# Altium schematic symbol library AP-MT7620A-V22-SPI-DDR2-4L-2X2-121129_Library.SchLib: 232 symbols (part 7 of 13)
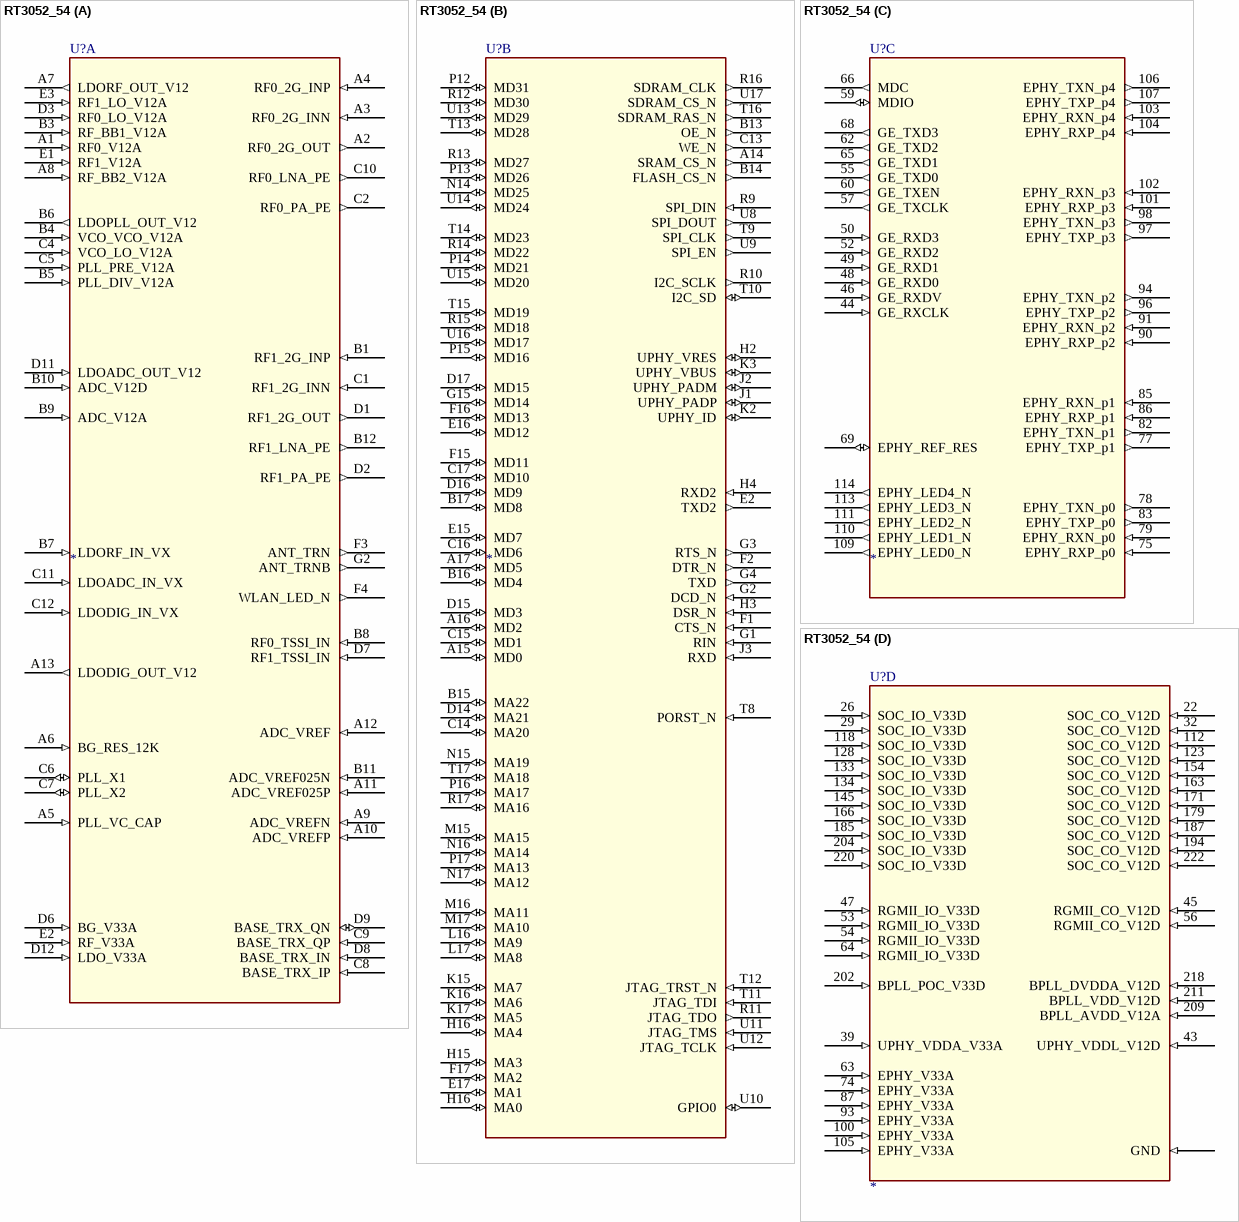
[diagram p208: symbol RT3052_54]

## RT3052_54
designator U?
footprint QFN285
part A pins: A1 RF0_V12A (in), A2 RF0_2G_OUT (out), A3 RF0_2G_INN (in), A4 RF0_2G_INP (in), A5 PLL_VC_CAP (in), A6 BG_RES_12K (in), A7 LDORF_OUT_V12 (out), A8 RF_BB2_V12A (in), A9 ADC_VREFN (in), A10 ADC_VREFP (in), A11 ADC_VREF025P (in), A12 ADC_VREF (in), A13 LDODIG_OUT_V12 (out), B1 RF1_2G_INP (in), B3 RF_BB1_V12A (in), B4 VCO_VCO_V12A (in), B5 PLL_DIV_V12A (in), B6 LDOPLL_OUT_V12 (out), B7 LDORF_IN_VX (in), B8 RF0_TSSI_IN (in), B9 ADC_V12A (in), B10 ADC_V12D (in), B11 ADC_VREF025N (in), B12 RF1_LNA_PE (out), C1 RF1_2G_INN (in), C2 RF0_PA_PE (out), C4 VCO_LO_V12A (in), C5 PLL_PRE_V12A (in), C6 PLL_X1 (io), C7 PLL_X2 (io), C8 BASE_TRX_IP (in), C9 BASE_TRX_QP (in), C10 RF0_LNA_PE (out), C11 LDOADC_IN_VX (in), C12 LDODIG_IN_VX (in), D1 RF1_2G_OUT (out), D2 RF1_PA_PE (out), D3 RF0_LO_V12A (in), D6 BG_V33A (in), D7 RF1_TSSI_IN (in), D8 BASE_TRX_IN (in), D9 BASE_TRX_QN (io), D11 LDOADC_OUT_V12 (in), D12 LDO_V33A (in), E1 RF1_V12A (in), E2 RF_V33A (in), E3 RF1_LO_V12A (in), F3 ANT_TRN (out), F4 WLAN_LED_N (out), G2 ANT_TRNB (out)
part B pins: A14 SRAM_CS_N (out), A15 MD0 (io), A16 MD2 (io), A17 MD5 (io), B13 OE_N (out), B14 FLASH_CS_N (out), B15 MA22 (io), B16 MD4 (io), B17 MD8 (io), C13 WE_N (out), C14 MA20 (io), C15 MD1 (io), C16 MD6 (io), C17 MD10 (io), D14 MA21 (io), D15 MD3 (io), D16 MD9 (io), D17 MD15 (io), E2 TXD2 (out), E15 MD7 (io), E16 MD12 (io), E17 MA1 (io), F1 CTS_N (in), F2 DTR_N (out), F15 MD11 (io), F16 MD13 (io), F17 MA2 (io), G1 RIN (in), G2 DCD_N (in), G3 RTS_N (out), G4 TXD (out), G15 MD14 (io), H2 UPHY_VRES (io), H3 DSR_N (in), H4 RXD2 (in), H15 MA3 (io), H16 MA4 (io), H16 MA0 (io), J1 UPHY_PADP (io), J2 UPHY_PADM (io), J3 RXD (in), K2 UPHY_ID (io), K3 UPHY_VBUS (io), K15 MA7 (io), K16 MA6 (io), K17 MA5 (io), L16 MA9 (io), L17 MA8 (io), M15 MA15 (io), M16 MA11 (io), M17 MA10 (io), N14 MD25 (io), N15 MA19 (io), N16 MA14 (io), N17 MA12 (io), P12 MD31 (io), P13 MD26 (io), P14 MD21 (io), P15 MD16 (io), P16 MA17 (io), P17 MA13 (io), R9 SPI_DIN (in), R10 I2C_SCLK (out), R11 JTAG_TDO (out), R12 MD30 (io), R13 MD27 (io), R14 MD22 (io), R15 MD18 (io), R16 SDRAM_CLK (out), R17 MA16 (io), T8 PORST_N (in), T9 SPI_CLK (out), T10 I2C_SD (io), T11 JTAG_TDI (in), T12 JTAG_TRST_N (in), T13 MD28 (io), T14 MD23 (io), T15 MD19 (io), T16 SDRAM_RAS_N (out), T17 MA18 (io), U8 SPI_DOUT (out), U9 SPI_EN (out), U10 GPIO0 (io), U11 JTAG_TMS (in), U12 JTAG_TCLK (in), U13 MD29 (io), U14 MD24 (io), U15 MD20 (io), U16 MD17 (io), U17 SDRAM_CS_N (out)
part C pins: 44 GE_RXCLK (in), 46 GE_RXDV (in), 48 GE_RXD0 (in), 49 GE_RXD1 (in), 50 GE_RXD3 (in), 52 GE_RXD2 (in), 55 GE_TXD0 (out), 57 GE_TXCLK (out), 59 MDIO (io), 60 GE_TXEN (out), 62 GE_TXD2 (out), 65 GE_TXD1 (out), 66 MDC (out), 68 GE_TXD3 (out), 69 EPHY_REF_RES (io), 75 EPHY_RXP_p0 (in), 77 EPHY_TXP_p1 (out), 78 EPHY_TXN_p0 (out), 79 EPHY_RXN_p0 (in), 82 EPHY_TXN_p1 (out), 83 EPHY_TXP_p0 (out), 85 EPHY_RXN_p1 (in), 86 EPHY_RXP_p1 (in), 90 EPHY_RXP_p2 (in), 91 EPHY_RXN_p2 (in), 94 EPHY_TXN_p2 (out), 96 EPHY_TXP_p2 (out), 97 EPHY_TXP_p3 (out), 98 EPHY_TXN_p3 (out), 101 EPHY_RXP_p3 (in), 102 EPHY_RXN_p3 (in), 103 EPHY_RXN_p4 (in), 104 EPHY_RXP_p4 (in), 106 EPHY_TXN_p4 (out), 107 EPHY_TXP_p4 (out), 109 EPHY_LED0_N (out), 110 EPHY_LED1_N (out), 111 EPHY_LED2_N (out), 113 EPHY_LED3_N (out), 114 EPHY_LED4_N (out)
part D pins: 22 SOC_CO_V12D (in), 26 SOC_IO_V33D (in), 29 SOC_IO_V33D (in), 32 SOC_CO_V12D (in), 39 UPHY_VDDA_V33A (in), 43 UPHY_VDDL_V12D (in), 45 RGMII_CO_V12D (in), 47 RGMII_IO_V33D (in), 53 RGMII_IO_V33D (in), 54 RGMII_IO_V33D (in), 56 RGMII_CO_V12D (in), 63 EPHY_V33A (in), 64 RGMII_IO_V33D (in), 74 EPHY_V33A (in), 87 EPHY_V33A (in), 93 EPHY_V33A (in), 100 EPHY_V33A (in), 105 EPHY_V33A (in), 112 SOC_CO_V12D (in), 118 SOC_IO_V33D (in), 123 SOC_CO_V12D (in), 128 SOC_IO_V33D (in), 133 SOC_IO_V33D (in), 134 SOC_IO_V33D (in), 145 SOC_IO_V33D (in), 154 SOC_CO_V12D (in), 163 SOC_CO_V12D (in), 166 SOC_IO_V33D (in), 171 SOC_CO_V12D (in), 179 SOC_CO_V12D (in), 185 SOC_IO_V33D (in), 187 SOC_CO_V12D (in), 194 SOC_CO_V12D (in), 202 BPLL_POC_V33D (in), 204 SOC_IO_V33D (in), 209 BPLL_AVDD_V12A (in), 211 BPLL_VDD_V12D (in), 218 BPLL_DVDDA_V12D (in), 220 SOC_IO_V33D (in), 222 SOC_CO_V12D (in), GND (in)

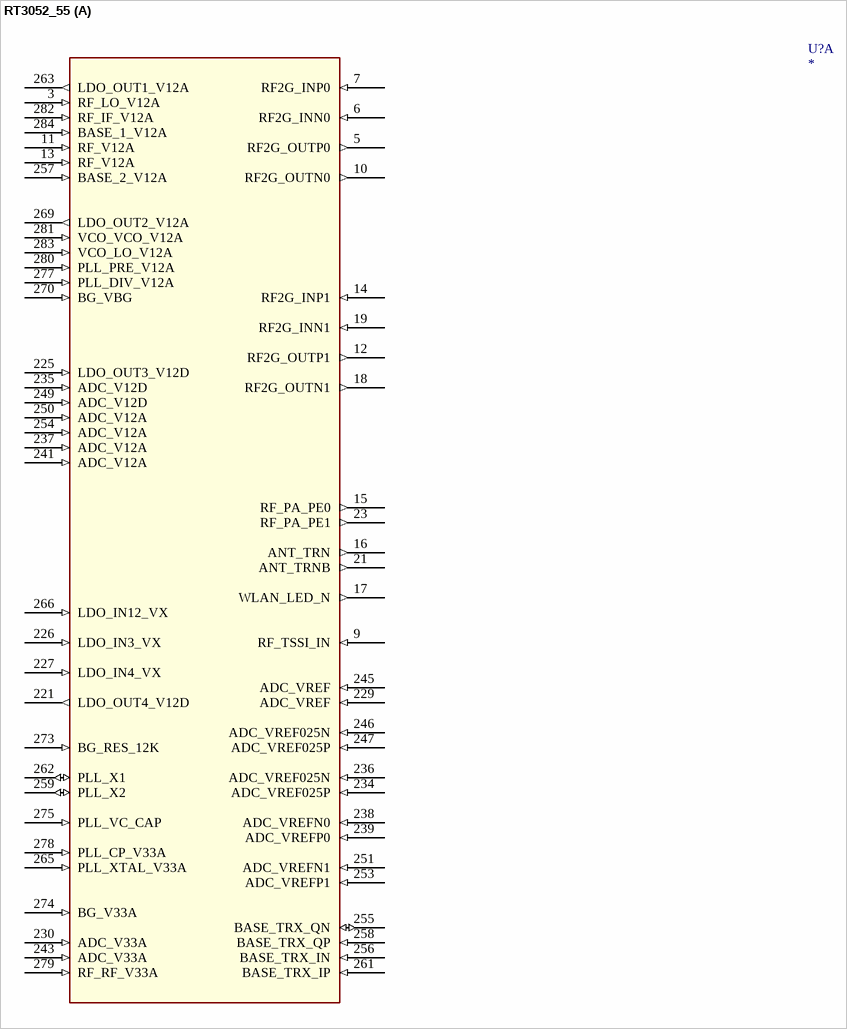
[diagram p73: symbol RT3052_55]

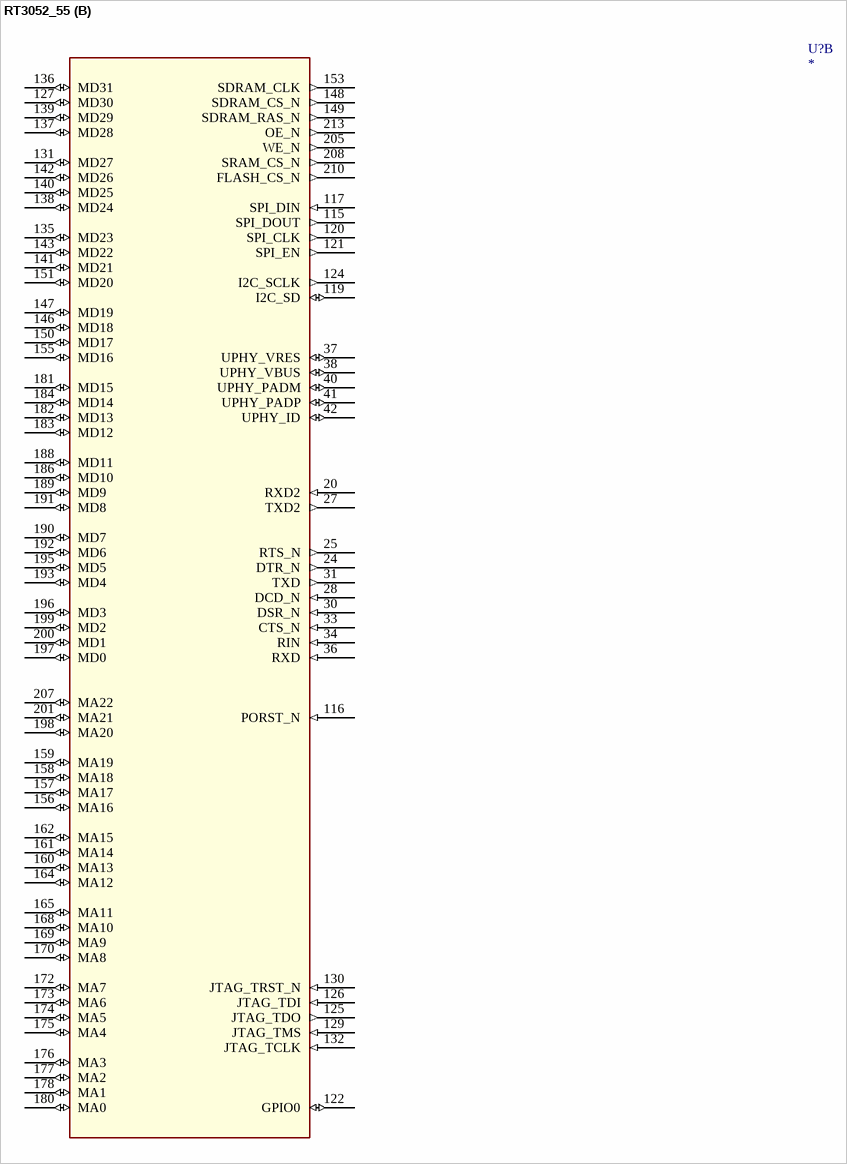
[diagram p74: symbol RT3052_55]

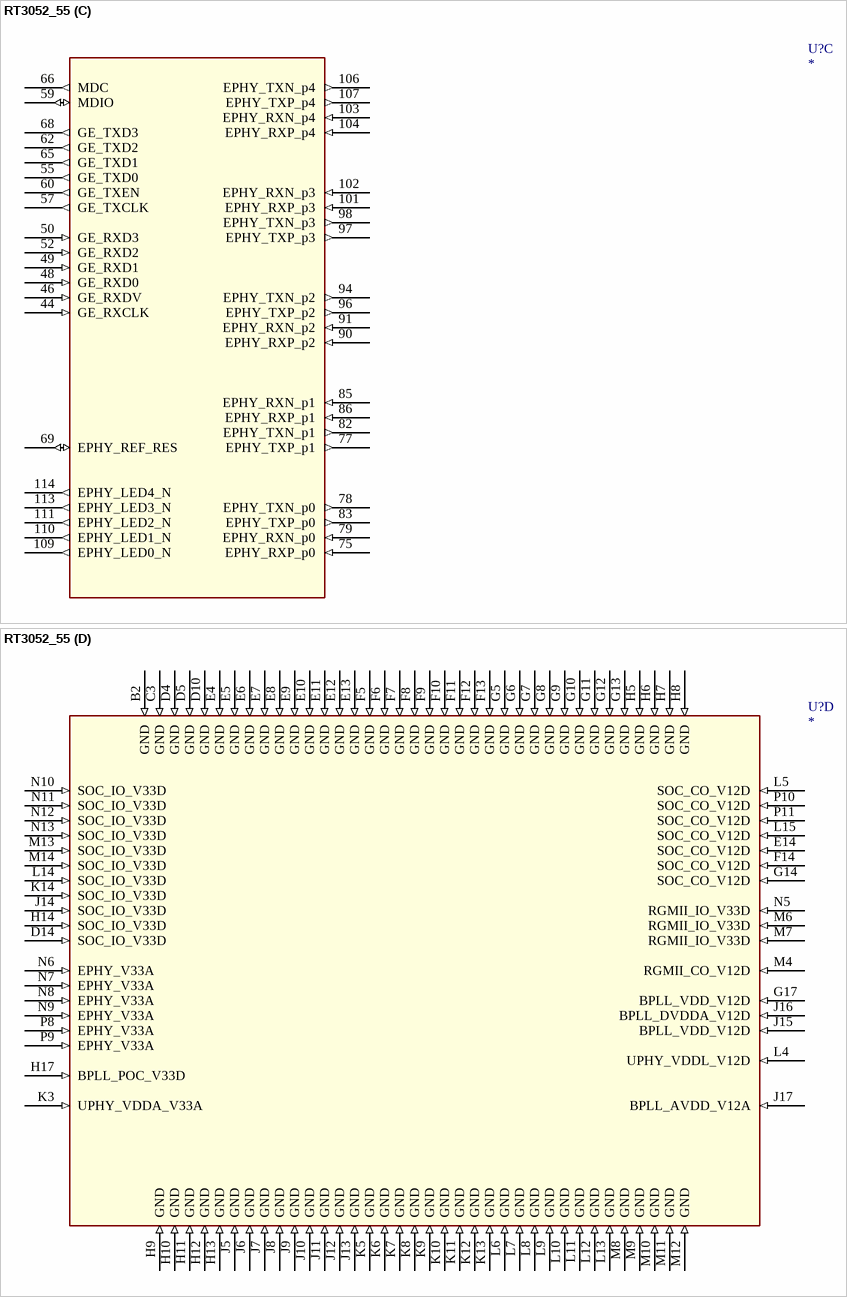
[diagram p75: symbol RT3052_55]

## RT3052_55
designator U?
footprint QFN285
part A pins: 3 RF_LO_V12A (in), 5 RF2G_OUTP0 (out), 6 RF2G_INN0 (in), 7 RF2G_INP0 (in), 9 RF_TSSI_IN (in), 10 RF2G_OUTN0 (out), 11 RF_V12A (in), 12 RF2G_OUTP1 (out), 13 RF_V12A (in), 14 RF2G_INP1 (in), 15 RF_PA_PE0 (out), 16 ANT_TRN (out), 17 WLAN_LED_N (out), 18 RF2G_OUTN1 (out), 19 RF2G_INN1 (in), 21 ANT_TRNB (out), 23 RF_PA_PE1 (out), 221 LDO_OUT4_V12D (out), 225 LDO_OUT3_V12D (in), 226 LDO_IN3_VX (in), 227 LDO_IN4_VX (in), 229 ADC_VREF (in), 230 ADC_V33A (in), 234 ADC_VREF025P (in), 235 ADC_V12D (in), 236 ADC_VREF025N (in), 237 ADC_V12A (in), 238 ADC_VREFN0 (in), 239 ADC_VREFP0 (in), 241 ADC_V12A (in), 243 ADC_V33A (in), 245 ADC_VREF (in), 246 ADC_VREF025N (in), 247 ADC_VREF025P (in), 249 ADC_V12D (in), 250 ADC_V12A (in), 251 ADC_VREFN1 (in), 253 ADC_VREFP1 (in), 254 ADC_V12A (in), 255 BASE_TRX_QN (io), 256 BASE_TRX_IN (in), 257 BASE_2_V12A (in), 258 BASE_TRX_QP (in), 259 PLL_X2 (io), 261 BASE_TRX_IP (in), 262 PLL_X1 (io), 263 LDO_OUT1_V12A (out), 265 PLL_XTAL_V33A (in), 266 LDO_IN12_VX (in), 269 LDO_OUT2_V12A (out), 270 BG_VBG (in), 273 BG_RES_12K (in), 274 BG_V33A (in), 275 PLL_VC_CAP (in), 277 PLL_DIV_V12A (in), 278 PLL_CP_V33A (in), 279 RF_RF_V33A (in), 280 PLL_PRE_V12A (in), 281 VCO_VCO_V12A (in), 282 RF_IF_V12A (in), 283 VCO_LO_V12A (in), 284 BASE_1_V12A (in)
part B pins: 20 RXD2 (in), 24 DTR_N (out), 25 RTS_N (out), 27 TXD2 (out), 28 DCD_N (in), 30 DSR_N (in), 31 TXD (out), 33 CTS_N (in), 34 RIN (in), 36 RXD (in), 37 UPHY_VRES (io), 38 UPHY_VBUS (io), 40 UPHY_PADM (io), 41 UPHY_PADP (io), 42 UPHY_ID (io), 115 SPI_DOUT (out), 116 PORST_N (in), 117 SPI_DIN (in), 119 I2C_SD (io), 120 SPI_CLK (out), 121 SPI_EN (out), 122 GPIO0 (io), 124 I2C_SCLK (out), 125 JTAG_TDO (out), 126 JTAG_TDI (in), 127 MD30 (io), 129 JTAG_TMS (in), 130 JTAG_TRST_N (in), 131 MD27 (io), 132 JTAG_TCLK (in), 135 MD23 (io), 136 MD31 (io), 137 MD28 (io), 138 MD24 (io), 139 MD29 (io), 140 MD25 (io), 141 MD21 (io), 142 MD26 (io), 143 MD22 (io), 146 MD18 (io), 147 MD19 (io), 148 SDRAM_CS_N (out), 149 SDRAM_RAS_N (out), 150 MD17 (io), 151 MD20 (io), 153 SDRAM_CLK (out), 155 MD16 (io), 156 MA16 (io), 157 MA17 (io), 158 MA18 (io), 159 MA19 (io), 160 MA13 (io), 161 MA14 (io), 162 MA15 (io), 164 MA12 (io), 165 MA11 (io), 168 MA10 (io), 169 MA9 (io), 170 MA8 (io), 172 MA7 (io), 173 MA6 (io), 174 MA5 (io), 175 MA4 (io), 176 MA3 (io), 177 MA2 (io), 178 MA1 (io), 180 MA0 (io), 181 MD15 (io), 182 MD13 (io), 183 MD12 (io), 184 MD14 (io), 186 MD10 (io), 188 MD11 (io), 189 MD9 (io), 190 MD7 (io), 191 MD8 (io), 192 MD6 (io), 193 MD4 (io), 195 MD5 (io), 196 MD3 (io), 197 MD0 (io), 198 MA20 (io), 199 MD2 (io), 200 MD1 (io), 201 MA21 (io), 205 WE_N (out), 207 MA22 (io), 208 SRAM_CS_N (out), 210 FLASH_CS_N (out), 213 OE_N (out)
part C pins: 44 GE_RXCLK (in), 46 GE_RXDV (in), 48 GE_RXD0 (in), 49 GE_RXD1 (in), 50 GE_RXD3 (in), 52 GE_RXD2 (in), 55 GE_TXD0 (out), 57 GE_TXCLK (out), 59 MDIO (io), 60 GE_TXEN (out), 62 GE_TXD2 (out), 65 GE_TXD1 (out), 66 MDC (out), 68 GE_TXD3 (out), 69 EPHY_REF_RES (io), 75 EPHY_RXP_p0 (in), 77 EPHY_TXP_p1 (out), 78 EPHY_TXN_p0 (out), 79 EPHY_RXN_p0 (in), 82 EPHY_TXN_p1 (out), 83 EPHY_TXP_p0 (out), 85 EPHY_RXN_p1 (in), 86 EPHY_RXP_p1 (in), 90 EPHY_RXP_p2 (in), 91 EPHY_RXN_p2 (in), 94 EPHY_TXN_p2 (out), 96 EPHY_TXP_p2 (out), 97 EPHY_TXP_p3 (out), 98 EPHY_TXN_p3 (out), 101 EPHY_RXP_p3 (in), 102 EPHY_RXN_p3 (in), 103 EPHY_RXN_p4 (in), 104 EPHY_RXP_p4 (in), 106 EPHY_TXN_p4 (out), 107 EPHY_TXP_p4 (out), 109 EPHY_LED0_N (out), 110 EPHY_LED1_N (out), 111 EPHY_LED2_N (out), 113 EPHY_LED3_N (out), 114 EPHY_LED4_N (out)
part D pins: B2 GND (in), C3 GND (in), D4 GND (in), D5 GND (in), D10 GND (in), D14 SOC_IO_V33D (in), E4 GND (in), E5 GND (in), E6 GND (in), E7 GND (in), E8 GND (in), E9 GND (in), E10 GND (in), E11 GND (in), E12 GND (in), E13 GND (in), E14 SOC_CO_V12D (in), F5 GND (in), F6 GND (in), F7 GND (in), F8 GND (in), F9 GND (in), F10 GND (in), F11 GND (in), F12 GND (in), F13 GND (in), F14 SOC_CO_V12D (in), G5 GND (in), G6 GND (in), G7 GND (in), G8 GND (in), G9 GND (in), G10 GND (in), G11 GND (in), G12 GND (in), G13 GND (in), G14 SOC_CO_V12D (in), G17 BPLL_VDD_V12D (in), H5 GND (in), H6 GND (in), H7 GND (in), H8 GND (in), H9 GND (in), H10 GND (in), H11 GND (in), H12 GND (in), H13 GND (in), H14 SOC_IO_V33D (in), H17 BPLL_POC_V33D (in), J5 GND (in), J6 GND (in), J7 GND (in), J8 GND (in), J9 GND (in), J10 GND (in), J11 GND (in), J12 GND (in), J13 GND (in), J14 SOC_IO_V33D (in), J15 BPLL_VDD_V12D (in), J16 BPLL_DVDDA_V12D (in), J17 BPLL_AVDD_V12A (in), K3 UPHY_VDDA_V33A (in), K5 GND (in), K6 GND (in), K7 GND (in), K8 GND (in), K9 GND (in), K10 GND (in), K11 GND (in), K12 GND (in), K13 GND (in), K14 SOC_IO_V33D (in), L4 UPHY_VDDL_V12D (in), L5 SOC_CO_V12D (in), L6 GND (in), L7 GND (in), L8 GND (in), L9 GND (in), L10 GND (in), L11 GND (in), L12 GND (in), L13 GND (in), L14 SOC_IO_V33D (in), L15 SOC_CO_V12D (in), M4 RGMII_CO_V12D (in), M6 RGMII_IO_V33D (in), M7 RGMII_IO_V33D (in), M8 GND (in), M9 GND (in), M10 GND (in), M11 GND (in), M12 GND (in), M13 SOC_IO_V33D (in), M14 SOC_IO_V33D (in), N5 RGMII_IO_V33D (in), N6 EPHY_V33A (in), N7 EPHY_V33A (in), N8 EPHY_V33A (in), N9 EPHY_V33A (in), N10 SOC_IO_V33D (in), N11 SOC_IO_V33D (in), N12 SOC_IO_V33D (in), N13 SOC_IO_V33D (in), P8 EPHY_V33A (in), P9 EPHY_V33A (in), P10 SOC_CO_V12D (in), P11 SOC_CO_V12D (in)

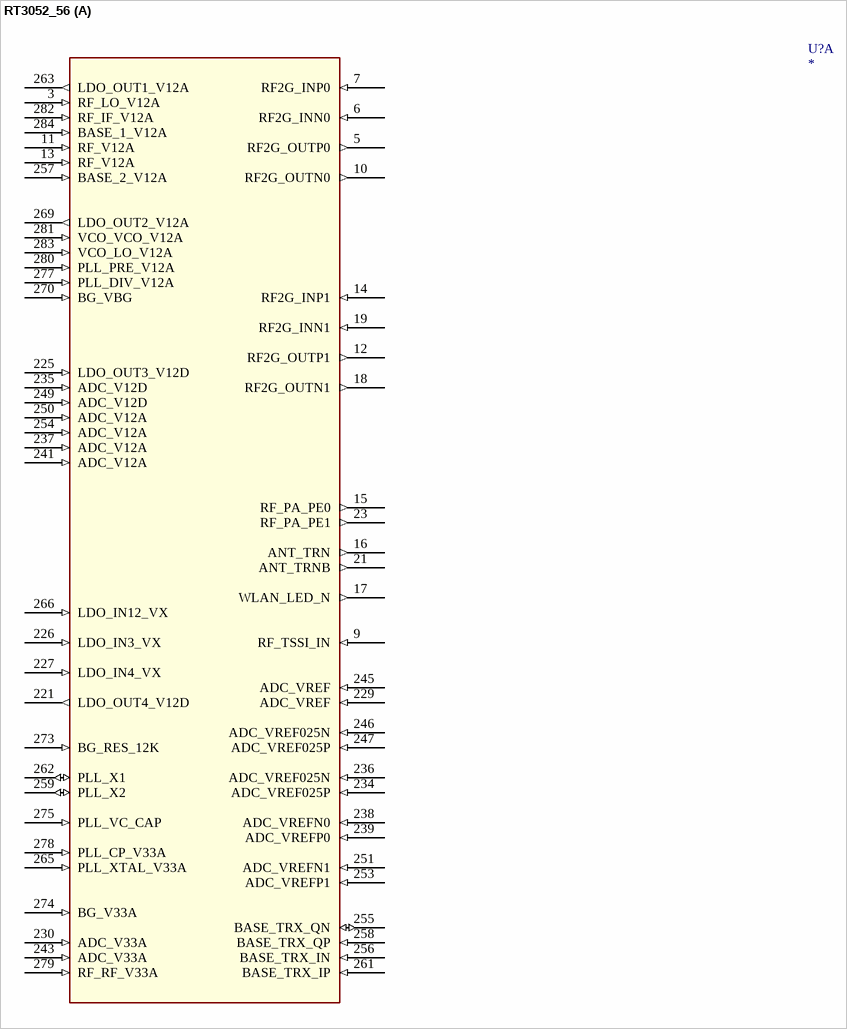
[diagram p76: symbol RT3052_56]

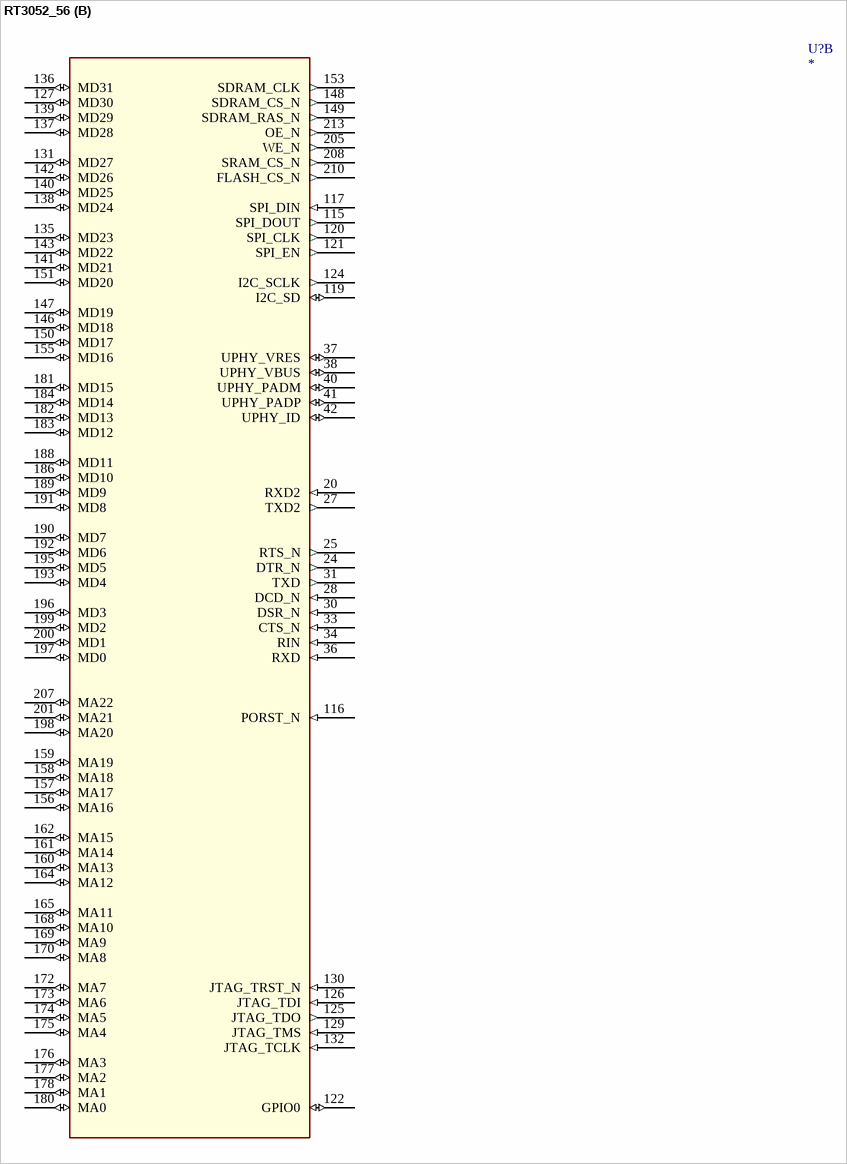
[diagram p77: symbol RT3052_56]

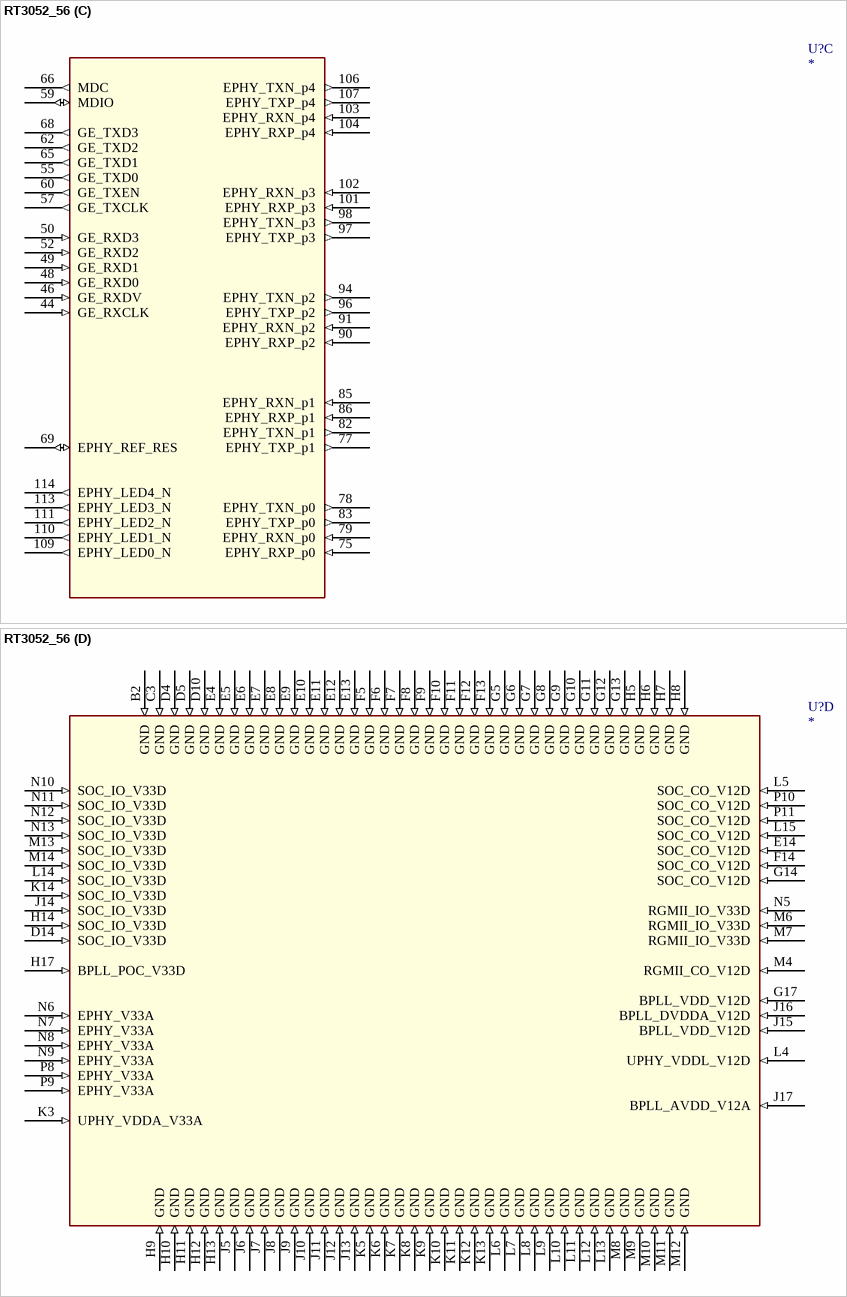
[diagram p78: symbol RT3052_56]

## RT3052_56
designator U?
footprint QFN285
part A pins: 3 RF_LO_V12A (in), 5 RF2G_OUTP0 (out), 6 RF2G_INN0 (in), 7 RF2G_INP0 (in), 9 RF_TSSI_IN (in), 10 RF2G_OUTN0 (out), 11 RF_V12A (in), 12 RF2G_OUTP1 (out), 13 RF_V12A (in), 14 RF2G_INP1 (in), 15 RF_PA_PE0 (out), 16 ANT_TRN (out), 17 WLAN_LED_N (out), 18 RF2G_OUTN1 (out), 19 RF2G_INN1 (in), 21 ANT_TRNB (out), 23 RF_PA_PE1 (out), 221 LDO_OUT4_V12D (out), 225 LDO_OUT3_V12D (in), 226 LDO_IN3_VX (in), 227 LDO_IN4_VX (in), 229 ADC_VREF (in), 230 ADC_V33A (in), 234 ADC_VREF025P (in), 235 ADC_V12D (in), 236 ADC_VREF025N (in), 237 ADC_V12A (in), 238 ADC_VREFN0 (in), 239 ADC_VREFP0 (in), 241 ADC_V12A (in), 243 ADC_V33A (in), 245 ADC_VREF (in), 246 ADC_VREF025N (in), 247 ADC_VREF025P (in), 249 ADC_V12D (in), 250 ADC_V12A (in), 251 ADC_VREFN1 (in), 253 ADC_VREFP1 (in), 254 ADC_V12A (in), 255 BASE_TRX_QN (io), 256 BASE_TRX_IN (in), 257 BASE_2_V12A (in), 258 BASE_TRX_QP (in), 259 PLL_X2 (io), 261 BASE_TRX_IP (in), 262 PLL_X1 (io), 263 LDO_OUT1_V12A (out), 265 PLL_XTAL_V33A (in), 266 LDO_IN12_VX (in), 269 LDO_OUT2_V12A (out), 270 BG_VBG (in), 273 BG_RES_12K (in), 274 BG_V33A (in), 275 PLL_VC_CAP (in), 277 PLL_DIV_V12A (in), 278 PLL_CP_V33A (in), 279 RF_RF_V33A (in), 280 PLL_PRE_V12A (in), 281 VCO_VCO_V12A (in), 282 RF_IF_V12A (in), 283 VCO_LO_V12A (in), 284 BASE_1_V12A (in)
part B pins: 20 RXD2 (in), 24 DTR_N (out), 25 RTS_N (out), 27 TXD2 (out), 28 DCD_N (in), 30 DSR_N (in), 31 TXD (out), 33 CTS_N (in), 34 RIN (in), 36 RXD (in), 37 UPHY_VRES (io), 38 UPHY_VBUS (io), 40 UPHY_PADM (io), 41 UPHY_PADP (io), 42 UPHY_ID (io), 115 SPI_DOUT (out), 116 PORST_N (in), 117 SPI_DIN (in), 119 I2C_SD (io), 120 SPI_CLK (out), 121 SPI_EN (out), 122 GPIO0 (io), 124 I2C_SCLK (out), 125 JTAG_TDO (out), 126 JTAG_TDI (in), 127 MD30 (io), 129 JTAG_TMS (in), 130 JTAG_TRST_N (in), 131 MD27 (io), 132 JTAG_TCLK (in), 135 MD23 (io), 136 MD31 (io), 137 MD28 (io), 138 MD24 (io), 139 MD29 (io), 140 MD25 (io), 141 MD21 (io), 142 MD26 (io), 143 MD22 (io), 146 MD18 (io), 147 MD19 (io), 148 SDRAM_CS_N (out), 149 SDRAM_RAS_N (out), 150 MD17 (io), 151 MD20 (io), 153 SDRAM_CLK (out), 155 MD16 (io), 156 MA16 (io), 157 MA17 (io), 158 MA18 (io), 159 MA19 (io), 160 MA13 (io), 161 MA14 (io), 162 MA15 (io), 164 MA12 (io), 165 MA11 (io), 168 MA10 (io), 169 MA9 (io), 170 MA8 (io), 172 MA7 (io), 173 MA6 (io), 174 MA5 (io), 175 MA4 (io), 176 MA3 (io), 177 MA2 (io), 178 MA1 (io), 180 MA0 (io), 181 MD15 (io), 182 MD13 (io), 183 MD12 (io), 184 MD14 (io), 186 MD10 (io), 188 MD11 (io), 189 MD9 (io), 190 MD7 (io), 191 MD8 (io), 192 MD6 (io), 193 MD4 (io), 195 MD5 (io), 196 MD3 (io), 197 MD0 (io), 198 MA20 (io), 199 MD2 (io), 200 MD1 (io), 201 MA21 (io), 205 WE_N (out), 207 MA22 (io), 208 SRAM_CS_N (out), 210 FLASH_CS_N (out), 213 OE_N (out)
part C pins: 44 GE_RXCLK (in), 46 GE_RXDV (in), 48 GE_RXD0 (in), 49 GE_RXD1 (in), 50 GE_RXD3 (in), 52 GE_RXD2 (in), 55 GE_TXD0 (out), 57 GE_TXCLK (out), 59 MDIO (io), 60 GE_TXEN (out), 62 GE_TXD2 (out), 65 GE_TXD1 (out), 66 MDC (out), 68 GE_TXD3 (out), 69 EPHY_REF_RES (io), 75 EPHY_RXP_p0 (in), 77 EPHY_TXP_p1 (out), 78 EPHY_TXN_p0 (out), 79 EPHY_RXN_p0 (in), 82 EPHY_TXN_p1 (out), 83 EPHY_TXP_p0 (out), 85 EPHY_RXN_p1 (in), 86 EPHY_RXP_p1 (in), 90 EPHY_RXP_p2 (in), 91 EPHY_RXN_p2 (in), 94 EPHY_TXN_p2 (out), 96 EPHY_TXP_p2 (out), 97 EPHY_TXP_p3 (out), 98 EPHY_TXN_p3 (out), 101 EPHY_RXP_p3 (in), 102 EPHY_RXN_p3 (in), 103 EPHY_RXN_p4 (in), 104 EPHY_RXP_p4 (in), 106 EPHY_TXN_p4 (out), 107 EPHY_TXP_p4 (out), 109 EPHY_LED0_N (out), 110 EPHY_LED1_N (out), 111 EPHY_LED2_N (out), 113 EPHY_LED3_N (out), 114 EPHY_LED4_N (out)
part D pins: B2 GND (in), C3 GND (in), D4 GND (in), D5 GND (in), D10 GND (in), D14 SOC_IO_V33D (in), E4 GND (in), E5 GND (in), E6 GND (in), E7 GND (in), E8 GND (in), E9 GND (in), E10 GND (in), E11 GND (in), E12 GND (in), E13 GND (in), E14 SOC_CO_V12D (in), F5 GND (in), F6 GND (in), F7 GND (in), F8 GND (in), F9 GND (in), F10 GND (in), F11 GND (in), F12 GND (in), F13 GND (in), F14 SOC_CO_V12D (in), G5 GND (in), G6 GND (in), G7 GND (in), G8 GND (in), G9 GND (in), G10 GND (in), G11 GND (in), G12 GND (in), G13 GND (in), G14 SOC_CO_V12D (in), G17 BPLL_VDD_V12D (in), H5 GND (in), H6 GND (in), H7 GND (in), H8 GND (in), H9 GND (in), H10 GND (in), H11 GND (in), H12 GND (in), H13 GND (in), H14 SOC_IO_V33D (in), H17 BPLL_POC_V33D (in), J5 GND (in), J6 GND (in), J7 GND (in), J8 GND (in), J9 GND (in), J10 GND (in), J11 GND (in), J12 GND (in), J13 GND (in), J14 SOC_IO_V33D (in), J15 BPLL_VDD_V12D (in), J16 BPLL_DVDDA_V12D (in), J17 BPLL_AVDD_V12A (in), K3 UPHY_VDDA_V33A (in), K5 GND (in), K6 GND (in), K7 GND (in), K8 GND (in), K9 GND (in), K10 GND (in), K11 GND (in), K12 GND (in), K13 GND (in), K14 SOC_IO_V33D (in), L4 UPHY_VDDL_V12D (in), L5 SOC_CO_V12D (in), L6 GND (in), L7 GND (in), L8 GND (in), L9 GND (in), L10 GND (in), L11 GND (in), L12 GND (in), L13 GND (in), L14 SOC_IO_V33D (in), L15 SOC_CO_V12D (in), M4 RGMII_CO_V12D (in), M6 RGMII_IO_V33D (in), M7 RGMII_IO_V33D (in), M8 GND (in), M9 GND (in), M10 GND (in), M11 GND (in), M12 GND (in), M13 SOC_IO_V33D (in), M14 SOC_IO_V33D (in), N5 RGMII_IO_V33D (in), N6 EPHY_V33A (in), N7 EPHY_V33A (in), N8 EPHY_V33A (in), N9 EPHY_V33A (in), N10 SOC_IO_V33D (in), N11 SOC_IO_V33D (in), N12 SOC_IO_V33D (in), N13 SOC_IO_V33D (in), P8 EPHY_V33A (in), P9 EPHY_V33A (in), P10 SOC_CO_V12D (in), P11 SOC_CO_V12D (in)

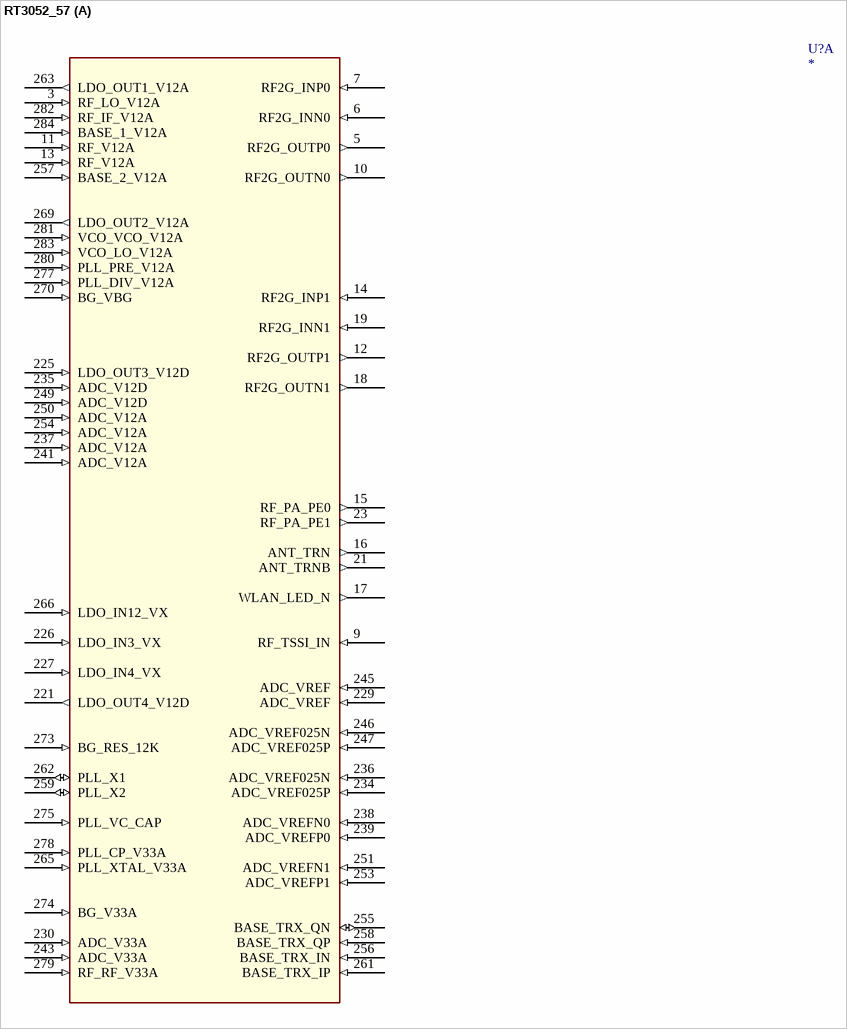
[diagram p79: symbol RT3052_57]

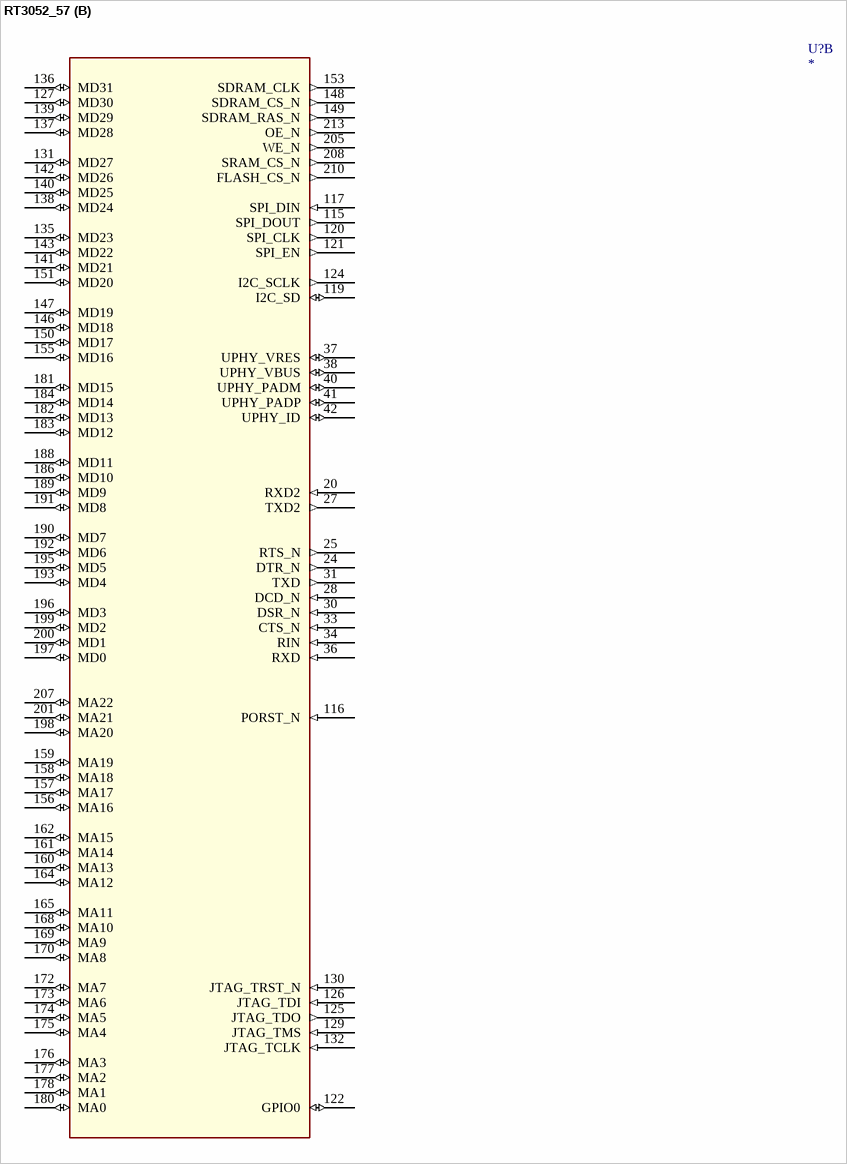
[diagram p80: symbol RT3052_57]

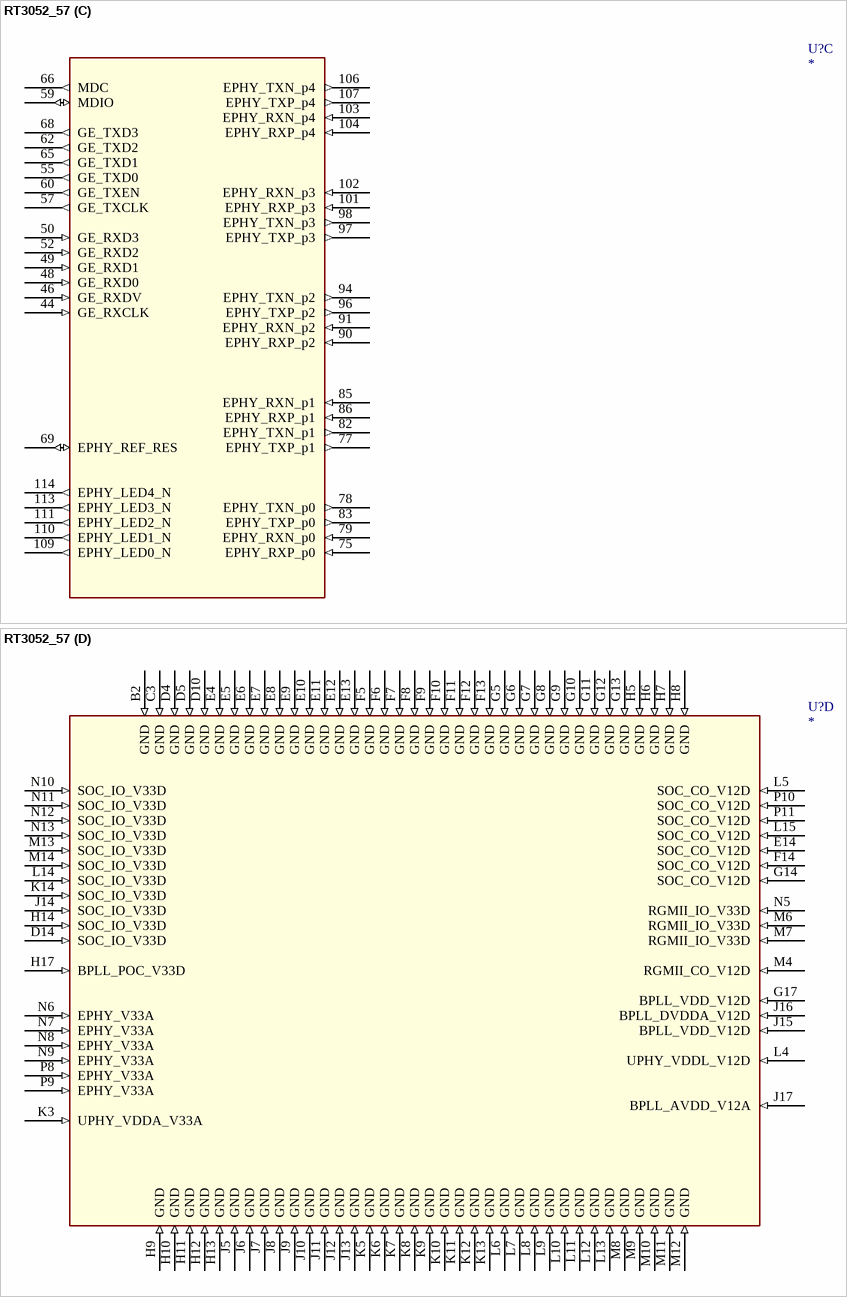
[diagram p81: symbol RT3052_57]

## RT3052_57
designator U?
footprint QFN285
part A pins: 3 RF_LO_V12A (in), 5 RF2G_OUTP0 (out), 6 RF2G_INN0 (in), 7 RF2G_INP0 (in), 9 RF_TSSI_IN (in), 10 RF2G_OUTN0 (out), 11 RF_V12A (in), 12 RF2G_OUTP1 (out), 13 RF_V12A (in), 14 RF2G_INP1 (in), 15 RF_PA_PE0 (out), 16 ANT_TRN (out), 17 WLAN_LED_N (out), 18 RF2G_OUTN1 (out), 19 RF2G_INN1 (in), 21 ANT_TRNB (out), 23 RF_PA_PE1 (out), 221 LDO_OUT4_V12D (out), 225 LDO_OUT3_V12D (in), 226 LDO_IN3_VX (in), 227 LDO_IN4_VX (in), 229 ADC_VREF (in), 230 ADC_V33A (in), 234 ADC_VREF025P (in), 235 ADC_V12D (in), 236 ADC_VREF025N (in), 237 ADC_V12A (in), 238 ADC_VREFN0 (in), 239 ADC_VREFP0 (in), 241 ADC_V12A (in), 243 ADC_V33A (in), 245 ADC_VREF (in), 246 ADC_VREF025N (in), 247 ADC_VREF025P (in), 249 ADC_V12D (in), 250 ADC_V12A (in), 251 ADC_VREFN1 (in), 253 ADC_VREFP1 (in), 254 ADC_V12A (in), 255 BASE_TRX_QN (io), 256 BASE_TRX_IN (in), 257 BASE_2_V12A (in), 258 BASE_TRX_QP (in), 259 PLL_X2 (io), 261 BASE_TRX_IP (in), 262 PLL_X1 (io), 263 LDO_OUT1_V12A (out), 265 PLL_XTAL_V33A (in), 266 LDO_IN12_VX (in), 269 LDO_OUT2_V12A (out), 270 BG_VBG (in), 273 BG_RES_12K (in), 274 BG_V33A (in), 275 PLL_VC_CAP (in), 277 PLL_DIV_V12A (in), 278 PLL_CP_V33A (in), 279 RF_RF_V33A (in), 280 PLL_PRE_V12A (in), 281 VCO_VCO_V12A (in), 282 RF_IF_V12A (in), 283 VCO_LO_V12A (in), 284 BASE_1_V12A (in)
part B pins: 20 RXD2 (in), 24 DTR_N (out), 25 RTS_N (out), 27 TXD2 (out), 28 DCD_N (in), 30 DSR_N (in), 31 TXD (out), 33 CTS_N (in), 34 RIN (in), 36 RXD (in), 37 UPHY_VRES (io), 38 UPHY_VBUS (io), 40 UPHY_PADM (io), 41 UPHY_PADP (io), 42 UPHY_ID (io), 115 SPI_DOUT (out), 116 PORST_N (in), 117 SPI_DIN (in), 119 I2C_SD (io), 120 SPI_CLK (out), 121 SPI_EN (out), 122 GPIO0 (io), 124 I2C_SCLK (out), 125 JTAG_TDO (out), 126 JTAG_TDI (in), 127 MD30 (io), 129 JTAG_TMS (in), 130 JTAG_TRST_N (in), 131 MD27 (io), 132 JTAG_TCLK (in), 135 MD23 (io), 136 MD31 (io), 137 MD28 (io), 138 MD24 (io), 139 MD29 (io), 140 MD25 (io), 141 MD21 (io), 142 MD26 (io), 143 MD22 (io), 146 MD18 (io), 147 MD19 (io), 148 SDRAM_CS_N (out), 149 SDRAM_RAS_N (out), 150 MD17 (io), 151 MD20 (io), 153 SDRAM_CLK (out), 155 MD16 (io), 156 MA16 (io), 157 MA17 (io), 158 MA18 (io), 159 MA19 (io), 160 MA13 (io), 161 MA14 (io), 162 MA15 (io), 164 MA12 (io), 165 MA11 (io), 168 MA10 (io), 169 MA9 (io), 170 MA8 (io), 172 MA7 (io), 173 MA6 (io), 174 MA5 (io), 175 MA4 (io), 176 MA3 (io), 177 MA2 (io), 178 MA1 (io), 180 MA0 (io), 181 MD15 (io), 182 MD13 (io), 183 MD12 (io), 184 MD14 (io), 186 MD10 (io), 188 MD11 (io), 189 MD9 (io), 190 MD7 (io), 191 MD8 (io), 192 MD6 (io), 193 MD4 (io), 195 MD5 (io), 196 MD3 (io), 197 MD0 (io), 198 MA20 (io), 199 MD2 (io), 200 MD1 (io), 201 MA21 (io), 205 WE_N (out), 207 MA22 (io), 208 SRAM_CS_N (out), 210 FLASH_CS_N (out), 213 OE_N (out)
part C pins: 44 GE_RXCLK (in), 46 GE_RXDV (in), 48 GE_RXD0 (in), 49 GE_RXD1 (in), 50 GE_RXD3 (in), 52 GE_RXD2 (in), 55 GE_TXD0 (out), 57 GE_TXCLK (out), 59 MDIO (io), 60 GE_TXEN (out), 62 GE_TXD2 (out), 65 GE_TXD1 (out), 66 MDC (out), 68 GE_TXD3 (out), 69 EPHY_REF_RES (io), 75 EPHY_RXP_p0 (in), 77 EPHY_TXP_p1 (out), 78 EPHY_TXN_p0 (out), 79 EPHY_RXN_p0 (in), 82 EPHY_TXN_p1 (out), 83 EPHY_TXP_p0 (out), 85 EPHY_RXN_p1 (in), 86 EPHY_RXP_p1 (in), 90 EPHY_RXP_p2 (in), 91 EPHY_RXN_p2 (in), 94 EPHY_TXN_p2 (out), 96 EPHY_TXP_p2 (out), 97 EPHY_TXP_p3 (out), 98 EPHY_TXN_p3 (out), 101 EPHY_RXP_p3 (in), 102 EPHY_RXN_p3 (in), 103 EPHY_RXN_p4 (in), 104 EPHY_RXP_p4 (in), 106 EPHY_TXN_p4 (out), 107 EPHY_TXP_p4 (out), 109 EPHY_LED0_N (out), 110 EPHY_LED1_N (out), 111 EPHY_LED2_N (out), 113 EPHY_LED3_N (out), 114 EPHY_LED4_N (out)
part D pins: B2 GND (in), C3 GND (in), D4 GND (in), D5 GND (in), D10 GND (in), D14 SOC_IO_V33D (in), E4 GND (in), E5 GND (in), E6 GND (in), E7 GND (in), E8 GND (in), E9 GND (in), E10 GND (in), E11 GND (in), E12 GND (in), E13 GND (in), E14 SOC_CO_V12D (in), F5 GND (in), F6 GND (in), F7 GND (in), F8 GND (in), F9 GND (in), F10 GND (in), F11 GND (in), F12 GND (in), F13 GND (in), F14 SOC_CO_V12D (in), G5 GND (in), G6 GND (in), G7 GND (in), G8 GND (in), G9 GND (in), G10 GND (in), G11 GND (in), G12 GND (in), G13 GND (in), G14 SOC_CO_V12D (in), G17 BPLL_VDD_V12D (in), H5 GND (in), H6 GND (in), H7 GND (in), H8 GND (in), H9 GND (in), H10 GND (in), H11 GND (in), H12 GND (in), H13 GND (in), H14 SOC_IO_V33D (in), H17 BPLL_POC_V33D (in), J5 GND (in), J6 GND (in), J7 GND (in), J8 GND (in), J9 GND (in), J10 GND (in), J11 GND (in), J12 GND (in), J13 GND (in), J14 SOC_IO_V33D (in), J15 BPLL_VDD_V12D (in), J16 BPLL_DVDDA_V12D (in), J17 BPLL_AVDD_V12A (in), K3 UPHY_VDDA_V33A (in), K5 GND (in), K6 GND (in), K7 GND (in), K8 GND (in), K9 GND (in), K10 GND (in), K11 GND (in), K12 GND (in), K13 GND (in), K14 SOC_IO_V33D (in), L4 UPHY_VDDL_V12D (in), L5 SOC_CO_V12D (in), L6 GND (in), L7 GND (in), L8 GND (in), L9 GND (in), L10 GND (in), L11 GND (in), L12 GND (in), L13 GND (in), L14 SOC_IO_V33D (in), L15 SOC_CO_V12D (in), M4 RGMII_CO_V12D (in), M6 RGMII_IO_V33D (in), M7 RGMII_IO_V33D (in), M8 GND (in), M9 GND (in), M10 GND (in), M11 GND (in), M12 GND (in), M13 SOC_IO_V33D (in), M14 SOC_IO_V33D (in), N5 RGMII_IO_V33D (in), N6 EPHY_V33A (in), N7 EPHY_V33A (in), N8 EPHY_V33A (in), N9 EPHY_V33A (in), N10 SOC_IO_V33D (in), N11 SOC_IO_V33D (in), N12 SOC_IO_V33D (in), N13 SOC_IO_V33D (in), P8 EPHY_V33A (in), P9 EPHY_V33A (in), P10 SOC_CO_V12D (in), P11 SOC_CO_V12D (in)

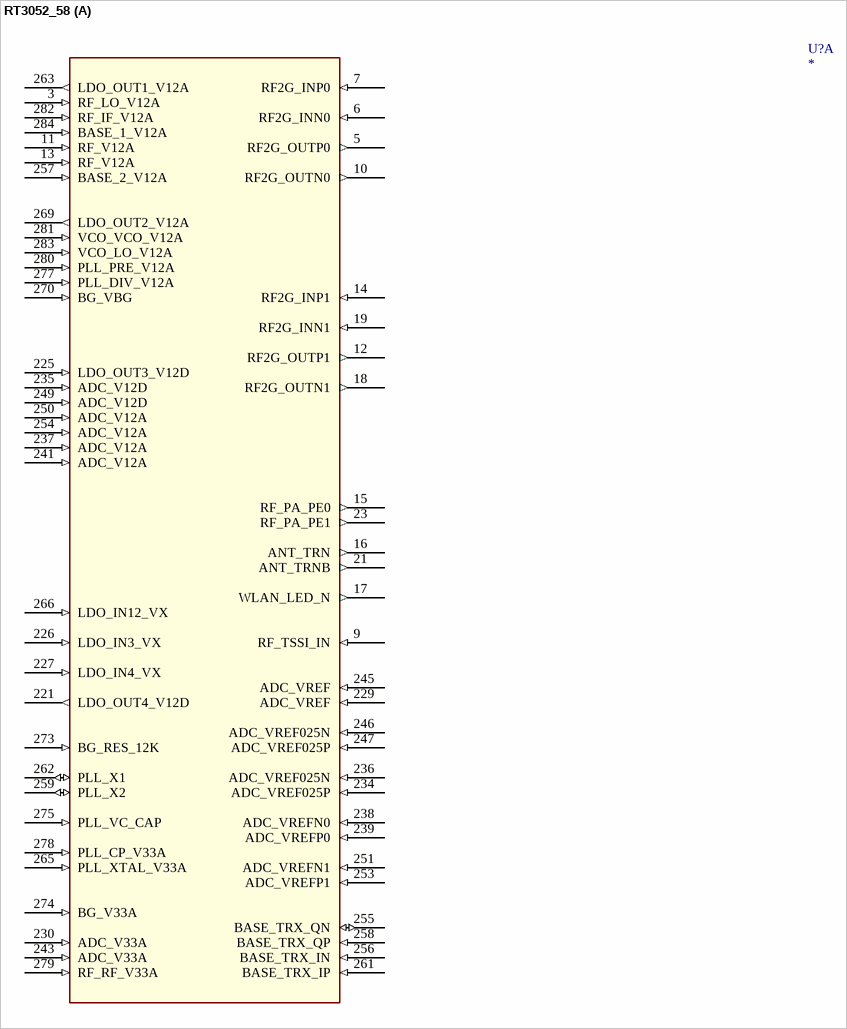
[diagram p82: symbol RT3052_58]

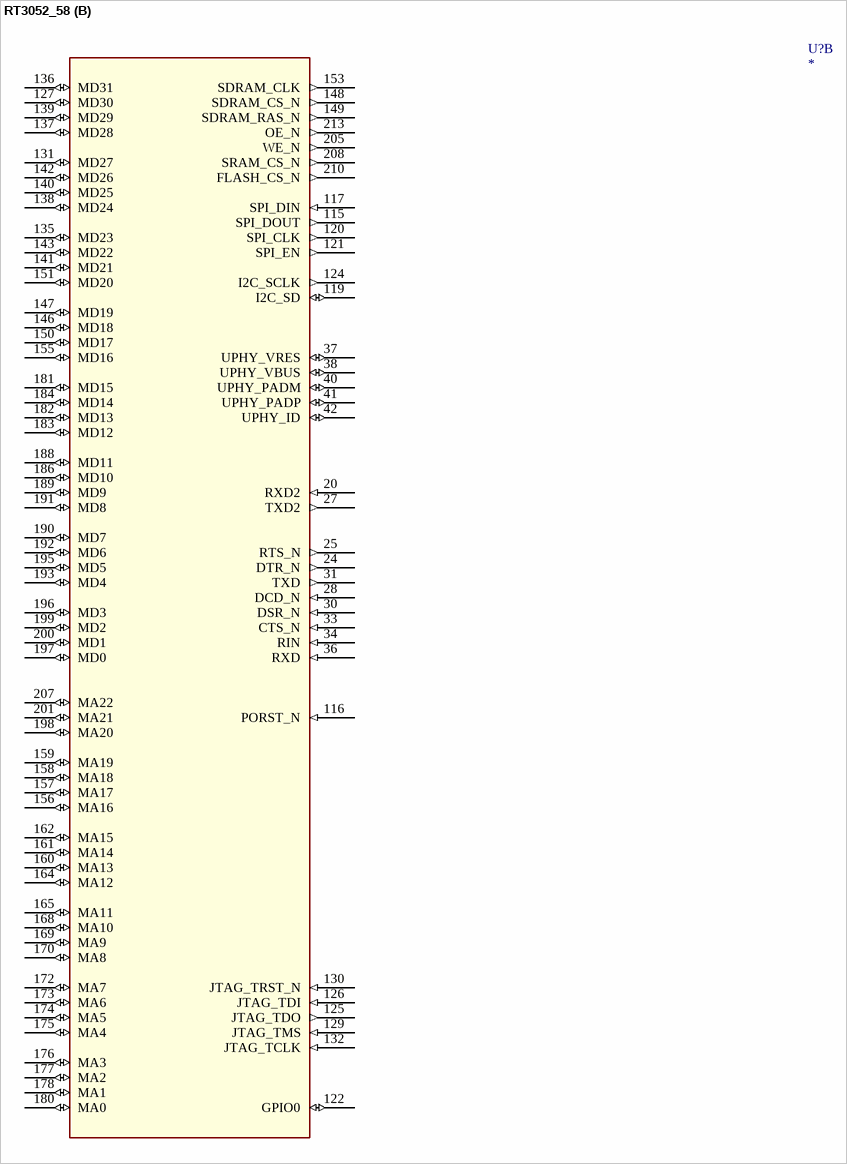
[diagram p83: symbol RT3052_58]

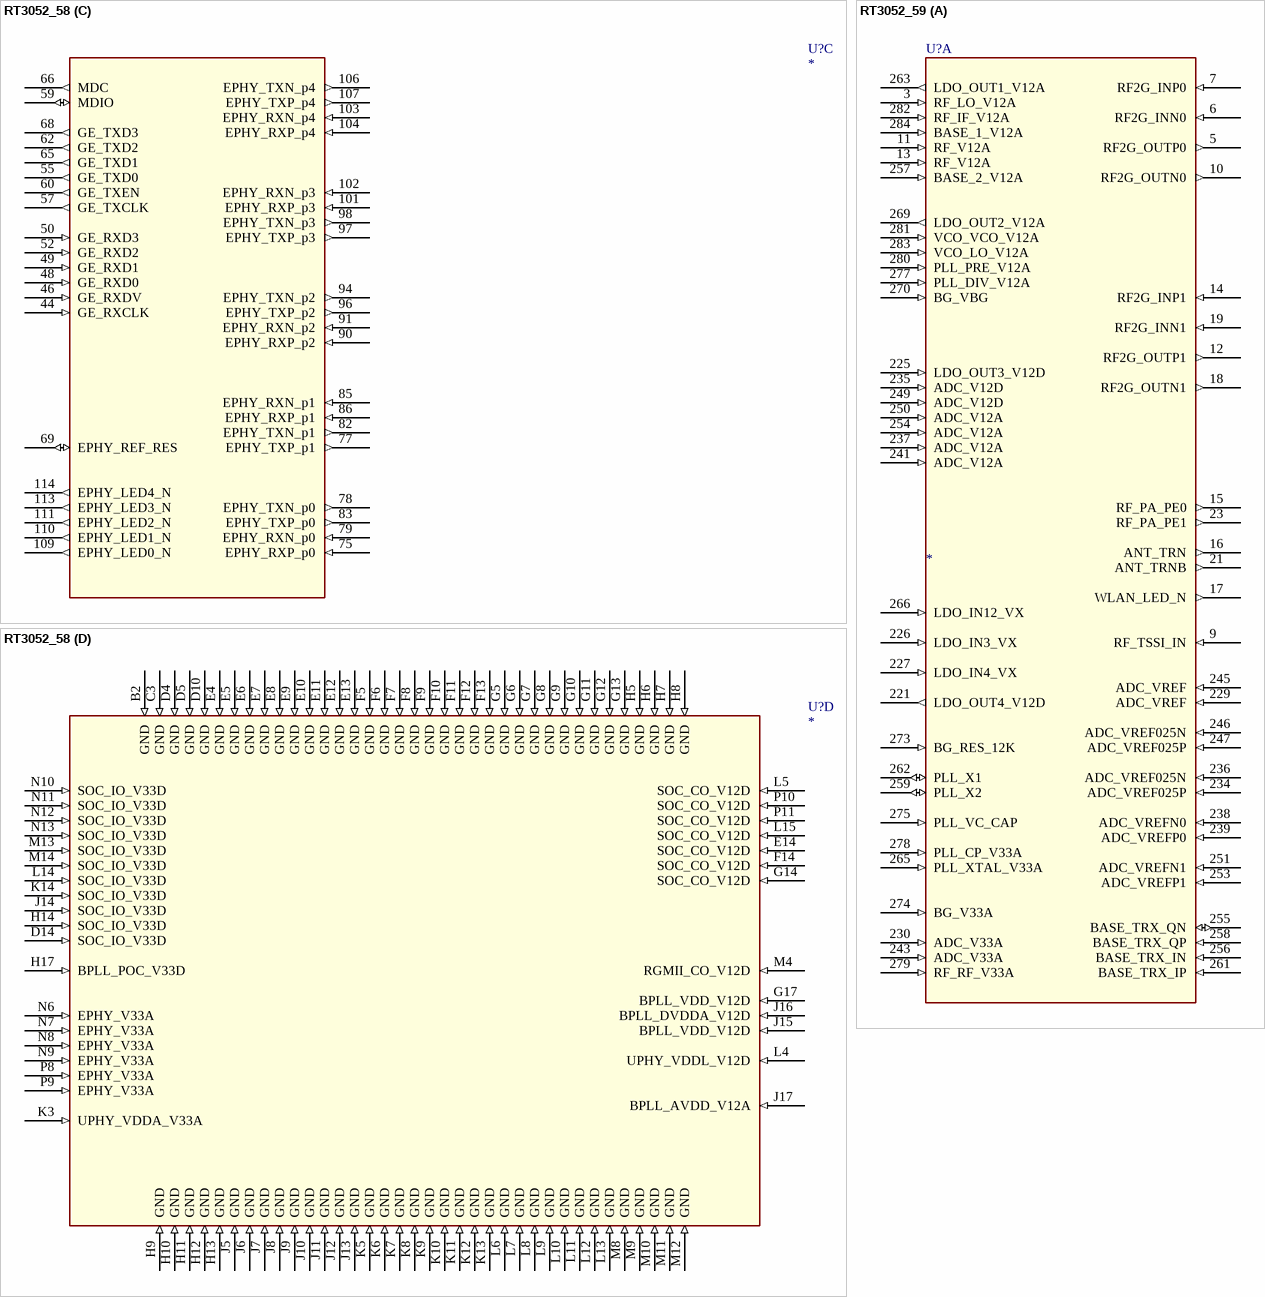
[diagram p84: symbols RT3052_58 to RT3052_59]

## RT3052_58
designator U?
footprint QFN285
part A pins: 3 RF_LO_V12A (in), 5 RF2G_OUTP0 (out), 6 RF2G_INN0 (in), 7 RF2G_INP0 (in), 9 RF_TSSI_IN (in), 10 RF2G_OUTN0 (out), 11 RF_V12A (in), 12 RF2G_OUTP1 (out), 13 RF_V12A (in), 14 RF2G_INP1 (in), 15 RF_PA_PE0 (out), 16 ANT_TRN (out), 17 WLAN_LED_N (out), 18 RF2G_OUTN1 (out), 19 RF2G_INN1 (in), 21 ANT_TRNB (out), 23 RF_PA_PE1 (out), 221 LDO_OUT4_V12D (out), 225 LDO_OUT3_V12D (in), 226 LDO_IN3_VX (in), 227 LDO_IN4_VX (in), 229 ADC_VREF (in), 230 ADC_V33A (in), 234 ADC_VREF025P (in), 235 ADC_V12D (in), 236 ADC_VREF025N (in), 237 ADC_V12A (in), 238 ADC_VREFN0 (in), 239 ADC_VREFP0 (in), 241 ADC_V12A (in), 243 ADC_V33A (in), 245 ADC_VREF (in), 246 ADC_VREF025N (in), 247 ADC_VREF025P (in), 249 ADC_V12D (in), 250 ADC_V12A (in), 251 ADC_VREFN1 (in), 253 ADC_VREFP1 (in), 254 ADC_V12A (in), 255 BASE_TRX_QN (io), 256 BASE_TRX_IN (in), 257 BASE_2_V12A (in), 258 BASE_TRX_QP (in), 259 PLL_X2 (io), 261 BASE_TRX_IP (in), 262 PLL_X1 (io), 263 LDO_OUT1_V12A (out), 265 PLL_XTAL_V33A (in), 266 LDO_IN12_VX (in), 269 LDO_OUT2_V12A (out), 270 BG_VBG (in), 273 BG_RES_12K (in), 274 BG_V33A (in), 275 PLL_VC_CAP (in), 277 PLL_DIV_V12A (in), 278 PLL_CP_V33A (in), 279 RF_RF_V33A (in), 280 PLL_PRE_V12A (in), 281 VCO_VCO_V12A (in), 282 RF_IF_V12A (in), 283 VCO_LO_V12A (in), 284 BASE_1_V12A (in)
part B pins: 20 RXD2 (in), 24 DTR_N (out), 25 RTS_N (out), 27 TXD2 (out), 28 DCD_N (in), 30 DSR_N (in), 31 TXD (out), 33 CTS_N (in), 34 RIN (in), 36 RXD (in), 37 UPHY_VRES (io), 38 UPHY_VBUS (io), 40 UPHY_PADM (io), 41 UPHY_PADP (io), 42 UPHY_ID (io), 115 SPI_DOUT (out), 116 PORST_N (in), 117 SPI_DIN (in), 119 I2C_SD (io), 120 SPI_CLK (out), 121 SPI_EN (out), 122 GPIO0 (io), 124 I2C_SCLK (out), 125 JTAG_TDO (out), 126 JTAG_TDI (in), 127 MD30 (io), 129 JTAG_TMS (in), 130 JTAG_TRST_N (in), 131 MD27 (io), 132 JTAG_TCLK (in), 135 MD23 (io), 136 MD31 (io), 137 MD28 (io), 138 MD24 (io), 139 MD29 (io), 140 MD25 (io), 141 MD21 (io), 142 MD26 (io), 143 MD22 (io), 146 MD18 (io), 147 MD19 (io), 148 SDRAM_CS_N (out), 149 SDRAM_RAS_N (out), 150 MD17 (io), 151 MD20 (io), 153 SDRAM_CLK (out), 155 MD16 (io), 156 MA16 (io), 157 MA17 (io), 158 MA18 (io), 159 MA19 (io), 160 MA13 (io), 161 MA14 (io), 162 MA15 (io), 164 MA12 (io), 165 MA11 (io), 168 MA10 (io), 169 MA9 (io), 170 MA8 (io), 172 MA7 (io), 173 MA6 (io), 174 MA5 (io), 175 MA4 (io), 176 MA3 (io), 177 MA2 (io), 178 MA1 (io), 180 MA0 (io), 181 MD15 (io), 182 MD13 (io), 183 MD12 (io), 184 MD14 (io), 186 MD10 (io), 188 MD11 (io), 189 MD9 (io), 190 MD7 (io), 191 MD8 (io), 192 MD6 (io), 193 MD4 (io), 195 MD5 (io), 196 MD3 (io), 197 MD0 (io), 198 MA20 (io), 199 MD2 (io), 200 MD1 (io), 201 MA21 (io), 205 WE_N (out), 207 MA22 (io), 208 SRAM_CS_N (out), 210 FLASH_CS_N (out), 213 OE_N (out)
part C pins: 44 GE_RXCLK (in), 46 GE_RXDV (in), 48 GE_RXD0 (in), 49 GE_RXD1 (in), 50 GE_RXD3 (in), 52 GE_RXD2 (in), 55 GE_TXD0 (out), 57 GE_TXCLK (out), 59 MDIO (io), 60 GE_TXEN (out), 62 GE_TXD2 (out), 65 GE_TXD1 (out), 66 MDC (out), 68 GE_TXD3 (out), 69 EPHY_REF_RES (io), 75 EPHY_RXP_p0 (in), 77 EPHY_TXP_p1 (out), 78 EPHY_TXN_p0 (out), 79 EPHY_RXN_p0 (in), 82 EPHY_TXN_p1 (out), 83 EPHY_TXP_p0 (out), 85 EPHY_RXN_p1 (in), 86 EPHY_RXP_p1 (in), 90 EPHY_RXP_p2 (in), 91 EPHY_RXN_p2 (in), 94 EPHY_TXN_p2 (out), 96 EPHY_TXP_p2 (out), 97 EPHY_TXP_p3 (out), 98 EPHY_TXN_p3 (out), 101 EPHY_RXP_p3 (in), 102 EPHY_RXN_p3 (in), 103 EPHY_RXN_p4 (in), 104 EPHY_RXP_p4 (in), 106 EPHY_TXN_p4 (out), 107 EPHY_TXP_p4 (out), 109 EPHY_LED0_N (out), 110 EPHY_LED1_N (out), 111 EPHY_LED2_N (out), 113 EPHY_LED3_N (out), 114 EPHY_LED4_N (out)
part D pins: B2 GND (in), C3 GND (in), D4 GND (in), D5 GND (in), D10 GND (in), D14 SOC_IO_V33D (in), E4 GND (in), E5 GND (in), E6 GND (in), E7 GND (in), E8 GND (in), E9 GND (in), E10 GND (in), E11 GND (in), E12 GND (in), E13 GND (in), E14 SOC_CO_V12D (in), F5 GND (in), F6 GND (in), F7 GND (in), F8 GND (in), F9 GND (in), F10 GND (in), F11 GND (in), F12 GND (in), F13 GND (in), F14 SOC_CO_V12D (in), G5 GND (in), G6 GND (in), G7 GND (in), G8 GND (in), G9 GND (in), G10 GND (in), G11 GND (in), G12 GND (in), G13 GND (in), G14 SOC_CO_V12D (in), G17 BPLL_VDD_V12D (in), H5 GND (in), H6 GND (in), H7 GND (in), H8 GND (in), H9 GND (in), H10 GND (in), H11 GND (in), H12 GND (in), H13 GND (in), H14 SOC_IO_V33D (in), H17 BPLL_POC_V33D (in), J5 GND (in), J6 GND (in), J7 GND (in), J8 GND (in), J9 GND (in), J10 GND (in), J11 GND (in), J12 GND (in), J13 GND (in), J14 SOC_IO_V33D (in), J15 BPLL_VDD_V12D (in), J16 BPLL_DVDDA_V12D (in), J17 BPLL_AVDD_V12A (in), K3 UPHY_VDDA_V33A (in), K5 GND (in), K6 GND (in), K7 GND (in), K8 GND (in), K9 GND (in), K10 GND (in), K11 GND (in), K12 GND (in), K13 GND (in), K14 SOC_IO_V33D (in), L4 UPHY_VDDL_V12D (in), L5 SOC_CO_V12D (in), L6 GND (in), L7 GND (in), L8 GND (in), L9 GND (in), L10 GND (in), L11 GND (in), L12 GND (in), L13 GND (in), L14 SOC_IO_V33D (in), L15 SOC_CO_V12D (in), M4 RGMII_CO_V12D (in), M8 GND (in), M9 GND (in), M10 GND (in), M11 GND (in), M12 GND (in), M13 SOC_IO_V33D (in), M14 SOC_IO_V33D (in), N6 EPHY_V33A (in), N7 EPHY_V33A (in), N8 EPHY_V33A (in), N9 EPHY_V33A (in), N10 SOC_IO_V33D (in), N11 SOC_IO_V33D (in), N12 SOC_IO_V33D (in), N13 SOC_IO_V33D (in), P8 EPHY_V33A (in), P9 EPHY_V33A (in), P10 SOC_CO_V12D (in), P11 SOC_CO_V12D (in)

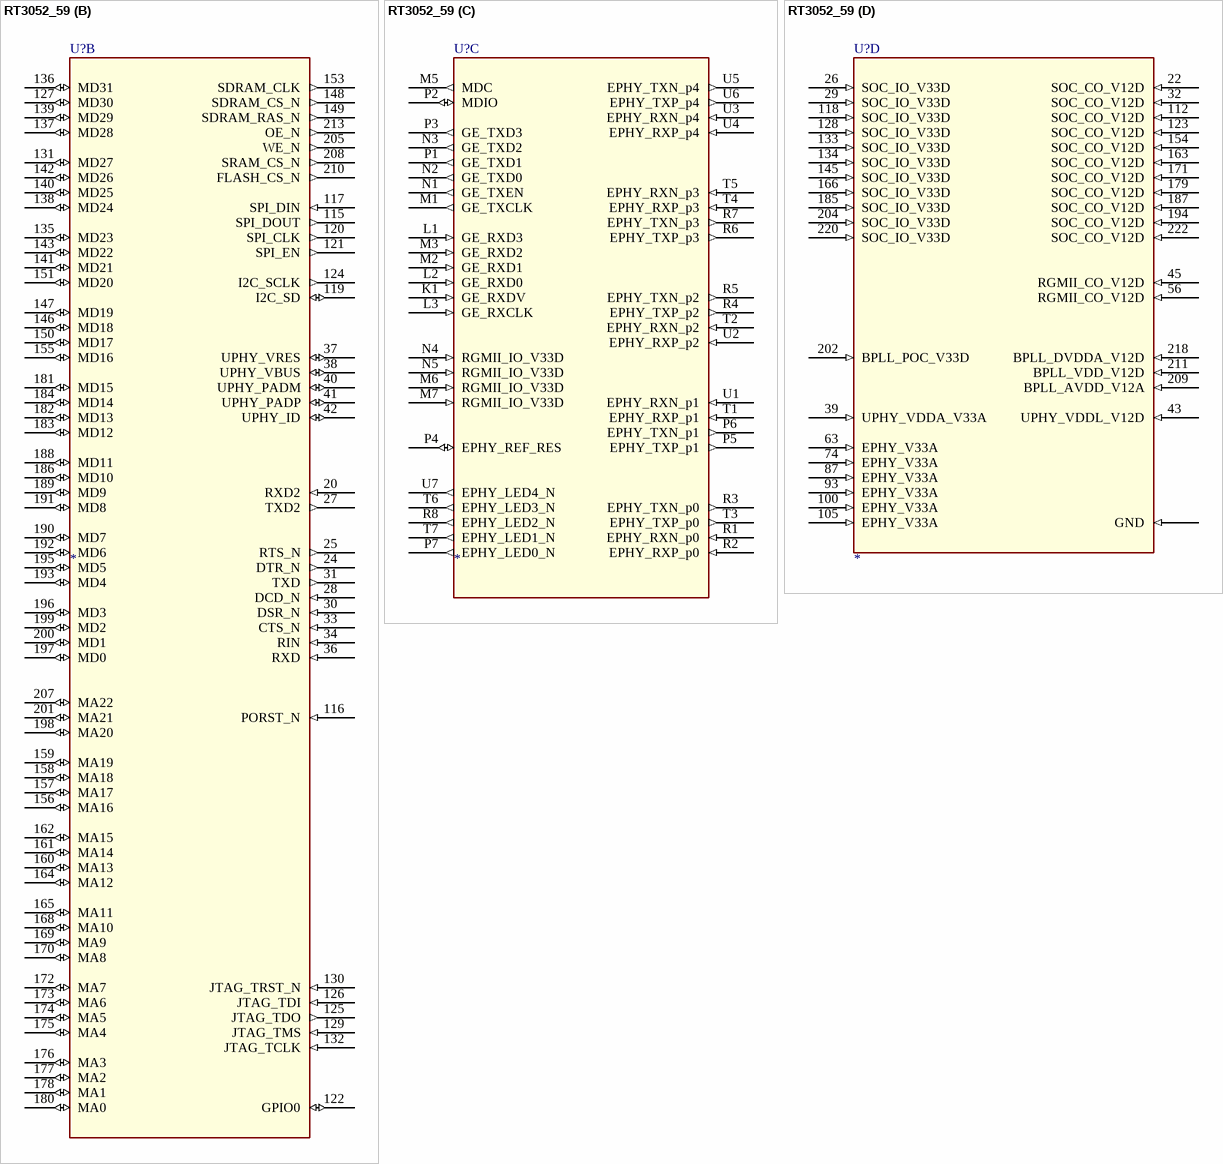
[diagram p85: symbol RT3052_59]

## RT3052_59
designator U?
footprint QFN285
part A pins: 3 RF_LO_V12A (in), 5 RF2G_OUTP0 (out), 6 RF2G_INN0 (in), 7 RF2G_INP0 (in), 9 RF_TSSI_IN (in), 10 RF2G_OUTN0 (out), 11 RF_V12A (in), 12 RF2G_OUTP1 (out), 13 RF_V12A (in), 14 RF2G_INP1 (in), 15 RF_PA_PE0 (out), 16 ANT_TRN (out), 17 WLAN_LED_N (out), 18 RF2G_OUTN1 (out), 19 RF2G_INN1 (in), 21 ANT_TRNB (out), 23 RF_PA_PE1 (out), 221 LDO_OUT4_V12D (out), 225 LDO_OUT3_V12D (in), 226 LDO_IN3_VX (in), 227 LDO_IN4_VX (in), 229 ADC_VREF (in), 230 ADC_V33A (in), 234 ADC_VREF025P (in), 235 ADC_V12D (in), 236 ADC_VREF025N (in), 237 ADC_V12A (in), 238 ADC_VREFN0 (in), 239 ADC_VREFP0 (in), 241 ADC_V12A (in), 243 ADC_V33A (in), 245 ADC_VREF (in), 246 ADC_VREF025N (in), 247 ADC_VREF025P (in), 249 ADC_V12D (in), 250 ADC_V12A (in), 251 ADC_VREFN1 (in), 253 ADC_VREFP1 (in), 254 ADC_V12A (in), 255 BASE_TRX_QN (io), 256 BASE_TRX_IN (in), 257 BASE_2_V12A (in), 258 BASE_TRX_QP (in), 259 PLL_X2 (io), 261 BASE_TRX_IP (in), 262 PLL_X1 (io), 263 LDO_OUT1_V12A (out), 265 PLL_XTAL_V33A (in), 266 LDO_IN12_VX (in), 269 LDO_OUT2_V12A (out), 270 BG_VBG (in), 273 BG_RES_12K (in), 274 BG_V33A (in), 275 PLL_VC_CAP (in), 277 PLL_DIV_V12A (in), 278 PLL_CP_V33A (in), 279 RF_RF_V33A (in), 280 PLL_PRE_V12A (in), 281 VCO_VCO_V12A (in), 282 RF_IF_V12A (in), 283 VCO_LO_V12A (in), 284 BASE_1_V12A (in)
part B pins: 20 RXD2 (in), 24 DTR_N (out), 25 RTS_N (out), 27 TXD2 (out), 28 DCD_N (in), 30 DSR_N (in), 31 TXD (out), 33 CTS_N (in), 34 RIN (in), 36 RXD (in), 37 UPHY_VRES (io), 38 UPHY_VBUS (io), 40 UPHY_PADM (io), 41 UPHY_PADP (io), 42 UPHY_ID (io), 115 SPI_DOUT (out), 116 PORST_N (in), 117 SPI_DIN (in), 119 I2C_SD (io), 120 SPI_CLK (out), 121 SPI_EN (out), 122 GPIO0 (io), 124 I2C_SCLK (out), 125 JTAG_TDO (out), 126 JTAG_TDI (in), 127 MD30 (io), 129 JTAG_TMS (in), 130 JTAG_TRST_N (in), 131 MD27 (io), 132 JTAG_TCLK (in), 135 MD23 (io), 136 MD31 (io), 137 MD28 (io), 138 MD24 (io), 139 MD29 (io), 140 MD25 (io), 141 MD21 (io), 142 MD26 (io), 143 MD22 (io), 146 MD18 (io), 147 MD19 (io), 148 SDRAM_CS_N (out), 149 SDRAM_RAS_N (out), 150 MD17 (io), 151 MD20 (io), 153 SDRAM_CLK (out), 155 MD16 (io), 156 MA16 (io), 157 MA17 (io), 158 MA18 (io), 159 MA19 (io), 160 MA13 (io), 161 MA14 (io), 162 MA15 (io), 164 MA12 (io), 165 MA11 (io), 168 MA10 (io), 169 MA9 (io), 170 MA8 (io), 172 MA7 (io), 173 MA6 (io), 174 MA5 (io), 175 MA4 (io), 176 MA3 (io), 177 MA2 (io), 178 MA1 (io), 180 MA0 (io), 181 MD15 (io), 182 MD13 (io), 183 MD12 (io), 184 MD14 (io), 186 MD10 (io), 188 MD11 (io), 189 MD9 (io), 190 MD7 (io), 191 MD8 (io), 192 MD6 (io), 193 MD4 (io), 195 MD5 (io), 196 MD3 (io), 197 MD0 (io), 198 MA20 (io), 199 MD2 (io), 200 MD1 (io), 201 MA21 (io), 205 WE_N (out), 207 MA22 (io), 208 SRAM_CS_N (out), 210 FLASH_CS_N (out), 213 OE_N (out)
part C pins: K1 GE_RXDV (in), L1 GE_RXD3 (in), L2 GE_RXD0 (in), L3 GE_RXCLK (in), M1 GE_TXCLK (out), M2 GE_RXD1 (in), M3 GE_RXD2 (in), M5 MDC (out), M6 RGMII_IO_V33D (in), M7 RGMII_IO_V33D (in), N1 GE_TXEN (out), N2 GE_TXD0 (out), N3 GE_TXD2 (out), N4 RGMII_IO_V33D (in), N5 RGMII_IO_V33D (in), P1 GE_TXD1 (out), P2 MDIO (io), P3 GE_TXD3 (out), P4 EPHY_REF_RES (io), P5 EPHY_TXP_p1 (out), P6 EPHY_TXN_p1 (out), P7 EPHY_LED0_N (out), R1 EPHY_RXN_p0 (in), R2 EPHY_RXP_p0 (in), R3 EPHY_TXN_p0 (out), R4 EPHY_TXP_p2 (out), R5 EPHY_TXN_p2 (out), R6 EPHY_TXP_p3 (out), R7 EPHY_TXN_p3 (out), R8 EPHY_LED2_N (out), T1 EPHY_RXP_p1 (in), T2 EPHY_RXN_p2 (in), T3 EPHY_TXP_p0 (out), T4 EPHY_RXP_p3 (in), T5 EPHY_RXN_p3 (in), T6 EPHY_LED3_N (out), T7 EPHY_LED1_N (out), U1 EPHY_RXN_p1 (in), U2 EPHY_RXP_p2 (in), U3 EPHY_RXN_p4 (in), U4 EPHY_RXP_p4 (in), U5 EPHY_TXN_p4 (out), U6 EPHY_TXP_p4 (out), U7 EPHY_LED4_N (out)
part D pins: 22 SOC_CO_V12D (in), 26 SOC_IO_V33D (in), 29 SOC_IO_V33D (in), 32 SOC_CO_V12D (in), 39 UPHY_VDDA_V33A (in), 43 UPHY_VDDL_V12D (in), 45 RGMII_CO_V12D (in), 56 RGMII_CO_V12D (in), 63 EPHY_V33A (in), 74 EPHY_V33A (in), 87 EPHY_V33A (in), 93 EPHY_V33A (in), 100 EPHY_V33A (in), 105 EPHY_V33A (in), 112 SOC_CO_V12D (in), 118 SOC_IO_V33D (in), 123 SOC_CO_V12D (in), 128 SOC_IO_V33D (in), 133 SOC_IO_V33D (in), 134 SOC_IO_V33D (in), 145 SOC_IO_V33D (in), 154 SOC_CO_V12D (in), 163 SOC_CO_V12D (in), 166 SOC_IO_V33D (in), 171 SOC_CO_V12D (in), 179 SOC_CO_V12D (in), 185 SOC_IO_V33D (in), 187 SOC_CO_V12D (in), 194 SOC_CO_V12D (in), 202 BPLL_POC_V33D (in), 204 SOC_IO_V33D (in), 209 BPLL_AVDD_V12A (in), 211 BPLL_VDD_V12D (in), 218 BPLL_DVDDA_V12D (in), 220 SOC_IO_V33D (in), 222 SOC_CO_V12D (in), GND (in)

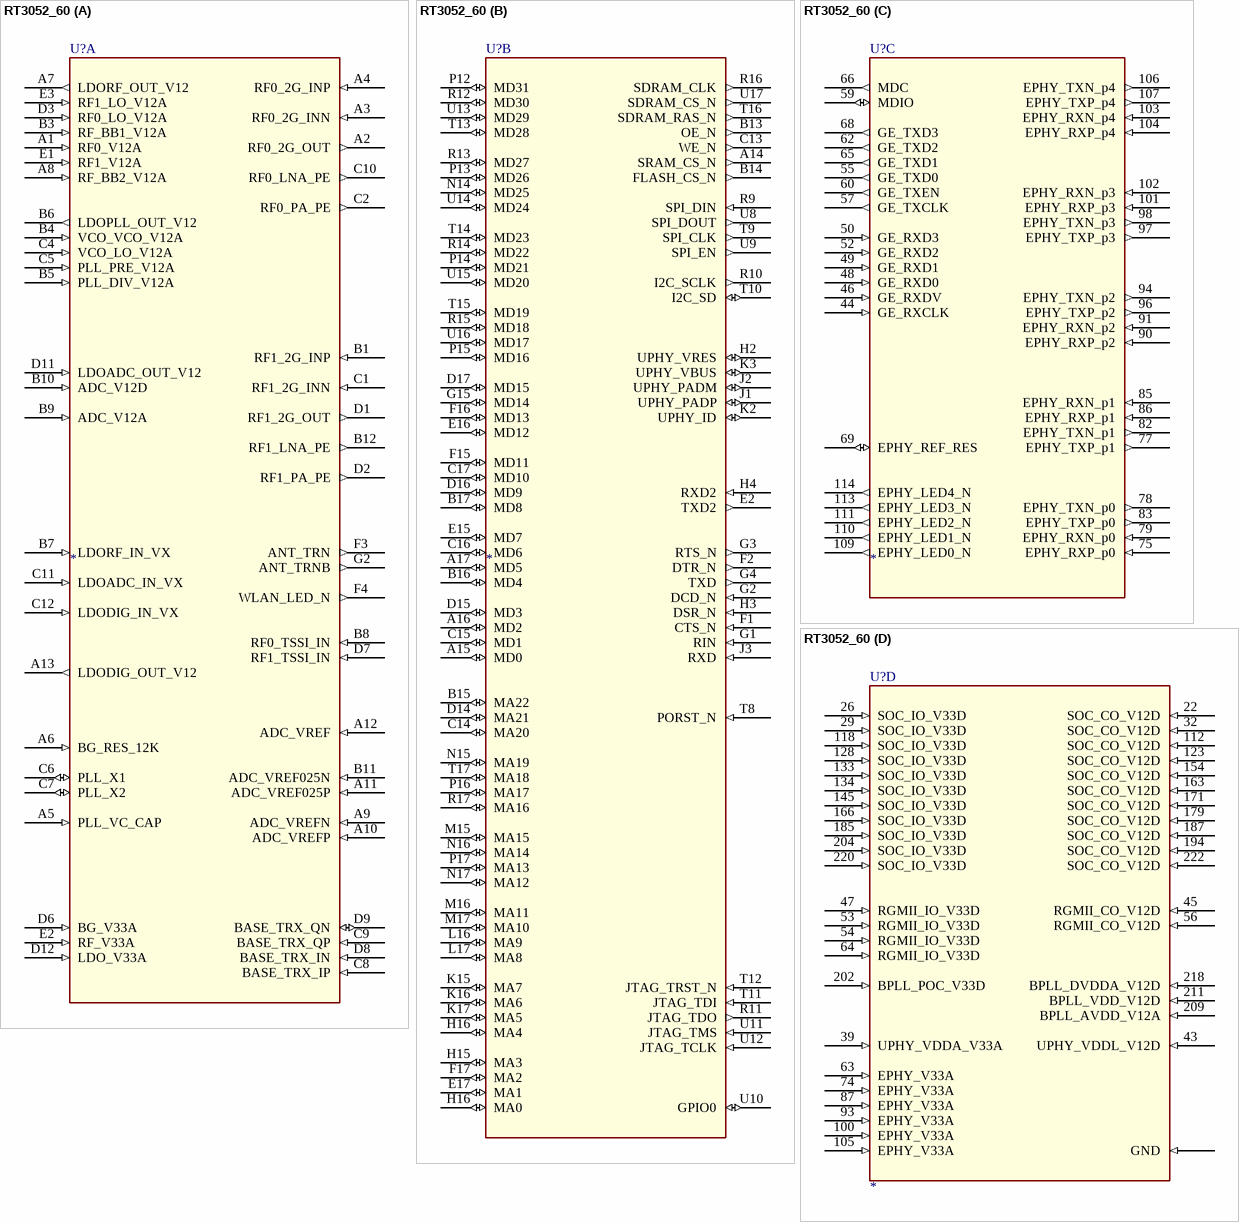
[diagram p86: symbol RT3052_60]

## RT3052_60
designator U?
footprint TFBGA289
part A pins: A1 RF0_V12A (in), A2 RF0_2G_OUT (out), A3 RF0_2G_INN (in), A4 RF0_2G_INP (in), A5 PLL_VC_CAP (in), A6 BG_RES_12K (in), A7 LDORF_OUT_V12 (out), A8 RF_BB2_V12A (in), A9 ADC_VREFN (in), A10 ADC_VREFP (in), A11 ADC_VREF025P (in), A12 ADC_VREF (in), A13 LDODIG_OUT_V12 (out), B1 RF1_2G_INP (in), B3 RF_BB1_V12A (in), B4 VCO_VCO_V12A (in), B5 PLL_DIV_V12A (in), B6 LDOPLL_OUT_V12 (out), B7 LDORF_IN_VX (in), B8 RF0_TSSI_IN (in), B9 ADC_V12A (in), B10 ADC_V12D (in), B11 ADC_VREF025N (in), B12 RF1_LNA_PE (out), C1 RF1_2G_INN (in), C2 RF0_PA_PE (out), C4 VCO_LO_V12A (in), C5 PLL_PRE_V12A (in), C6 PLL_X1 (io), C7 PLL_X2 (io), C8 BASE_TRX_IP (in), C9 BASE_TRX_QP (in), C10 RF0_LNA_PE (out), C11 LDOADC_IN_VX (in), C12 LDODIG_IN_VX (in), D1 RF1_2G_OUT (out), D2 RF1_PA_PE (out), D3 RF0_LO_V12A (in), D6 BG_V33A (in), D7 RF1_TSSI_IN (in), D8 BASE_TRX_IN (in), D9 BASE_TRX_QN (io), D11 LDOADC_OUT_V12 (in), D12 LDO_V33A (in), E1 RF1_V12A (in), E2 RF_V33A (in), E3 RF1_LO_V12A (in), F3 ANT_TRN (out), F4 WLAN_LED_N (out), G2 ANT_TRNB (out)
part B pins: A14 SRAM_CS_N (out), A15 MD0 (io), A16 MD2 (io), A17 MD5 (io), B13 OE_N (out), B14 FLASH_CS_N (out), B15 MA22 (io), B16 MD4 (io), B17 MD8 (io), C13 WE_N (out), C14 MA20 (io), C15 MD1 (io), C16 MD6 (io), C17 MD10 (io), D14 MA21 (io), D15 MD3 (io), D16 MD9 (io), D17 MD15 (io), E2 TXD2 (out), E15 MD7 (io), E16 MD12 (io), E17 MA1 (io), F1 CTS_N (in), F2 DTR_N (out), F15 MD11 (io), F16 MD13 (io), F17 MA2 (io), G1 RIN (in), G2 DCD_N (in), G3 RTS_N (out), G4 TXD (out), G15 MD14 (io), H2 UPHY_VRES (io), H3 DSR_N (in), H4 RXD2 (in), H15 MA3 (io), H16 MA4 (io), H16 MA0 (io), J1 UPHY_PADP (io), J2 UPHY_PADM (io), J3 RXD (in), K2 UPHY_ID (io), K3 UPHY_VBUS (io), K15 MA7 (io), K16 MA6 (io), K17 MA5 (io), L16 MA9 (io), L17 MA8 (io), M15 MA15 (io), M16 MA11 (io), M17 MA10 (io), N14 MD25 (io), N15 MA19 (io), N16 MA14 (io), N17 MA12 (io), P12 MD31 (io), P13 MD26 (io), P14 MD21 (io), P15 MD16 (io), P16 MA17 (io), P17 MA13 (io), R9 SPI_DIN (in), R10 I2C_SCLK (out), R11 JTAG_TDO (out), R12 MD30 (io), R13 MD27 (io), R14 MD22 (io), R15 MD18 (io), R16 SDRAM_CLK (out), R17 MA16 (io), T8 PORST_N (in), T9 SPI_CLK (out), T10 I2C_SD (io), T11 JTAG_TDI (in), T12 JTAG_TRST_N (in), T13 MD28 (io), T14 MD23 (io), T15 MD19 (io), T16 SDRAM_RAS_N (out), T17 MA18 (io), U8 SPI_DOUT (out), U9 SPI_EN (out), U10 GPIO0 (io), U11 JTAG_TMS (in), U12 JTAG_TCLK (in), U13 MD29 (io), U14 MD24 (io), U15 MD20 (io), U16 MD17 (io), U17 SDRAM_CS_N (out)
part C pins: 44 GE_RXCLK (in), 46 GE_RXDV (in), 48 GE_RXD0 (in), 49 GE_RXD1 (in), 50 GE_RXD3 (in), 52 GE_RXD2 (in), 55 GE_TXD0 (out), 57 GE_TXCLK (out), 59 MDIO (io), 60 GE_TXEN (out), 62 GE_TXD2 (out), 65 GE_TXD1 (out), 66 MDC (out), 68 GE_TXD3 (out), 69 EPHY_REF_RES (io), 75 EPHY_RXP_p0 (in), 77 EPHY_TXP_p1 (out), 78 EPHY_TXN_p0 (out), 79 EPHY_RXN_p0 (in), 82 EPHY_TXN_p1 (out), 83 EPHY_TXP_p0 (out), 85 EPHY_RXN_p1 (in), 86 EPHY_RXP_p1 (in), 90 EPHY_RXP_p2 (in), 91 EPHY_RXN_p2 (in), 94 EPHY_TXN_p2 (out), 96 EPHY_TXP_p2 (out), 97 EPHY_TXP_p3 (out), 98 EPHY_TXN_p3 (out), 101 EPHY_RXP_p3 (in), 102 EPHY_RXN_p3 (in), 103 EPHY_RXN_p4 (in), 104 EPHY_RXP_p4 (in), 106 EPHY_TXN_p4 (out), 107 EPHY_TXP_p4 (out), 109 EPHY_LED0_N (out), 110 EPHY_LED1_N (out), 111 EPHY_LED2_N (out), 113 EPHY_LED3_N (out), 114 EPHY_LED4_N (out)
part D pins: 22 SOC_CO_V12D (in), 26 SOC_IO_V33D (in), 29 SOC_IO_V33D (in), 32 SOC_CO_V12D (in), 39 UPHY_VDDA_V33A (in), 43 UPHY_VDDL_V12D (in), 45 RGMII_CO_V12D (in), 47 RGMII_IO_V33D (in), 53 RGMII_IO_V33D (in), 54 RGMII_IO_V33D (in), 56 RGMII_CO_V12D (in), 63 EPHY_V33A (in), 64 RGMII_IO_V33D (in), 74 EPHY_V33A (in), 87 EPHY_V33A (in), 93 EPHY_V33A (in), 100 EPHY_V33A (in), 105 EPHY_V33A (in), 112 SOC_CO_V12D (in), 118 SOC_IO_V33D (in), 123 SOC_CO_V12D (in), 128 SOC_IO_V33D (in), 133 SOC_IO_V33D (in), 134 SOC_IO_V33D (in), 145 SOC_IO_V33D (in), 154 SOC_CO_V12D (in), 163 SOC_CO_V12D (in), 166 SOC_IO_V33D (in), 171 SOC_CO_V12D (in), 179 SOC_CO_V12D (in), 185 SOC_IO_V33D (in), 187 SOC_CO_V12D (in), 194 SOC_CO_V12D (in), 202 BPLL_POC_V33D (in), 204 SOC_IO_V33D (in), 209 BPLL_AVDD_V12A (in), 211 BPLL_VDD_V12D (in), 218 BPLL_DVDDA_V12D (in), 220 SOC_IO_V33D (in), 222 SOC_CO_V12D (in), GND (in)

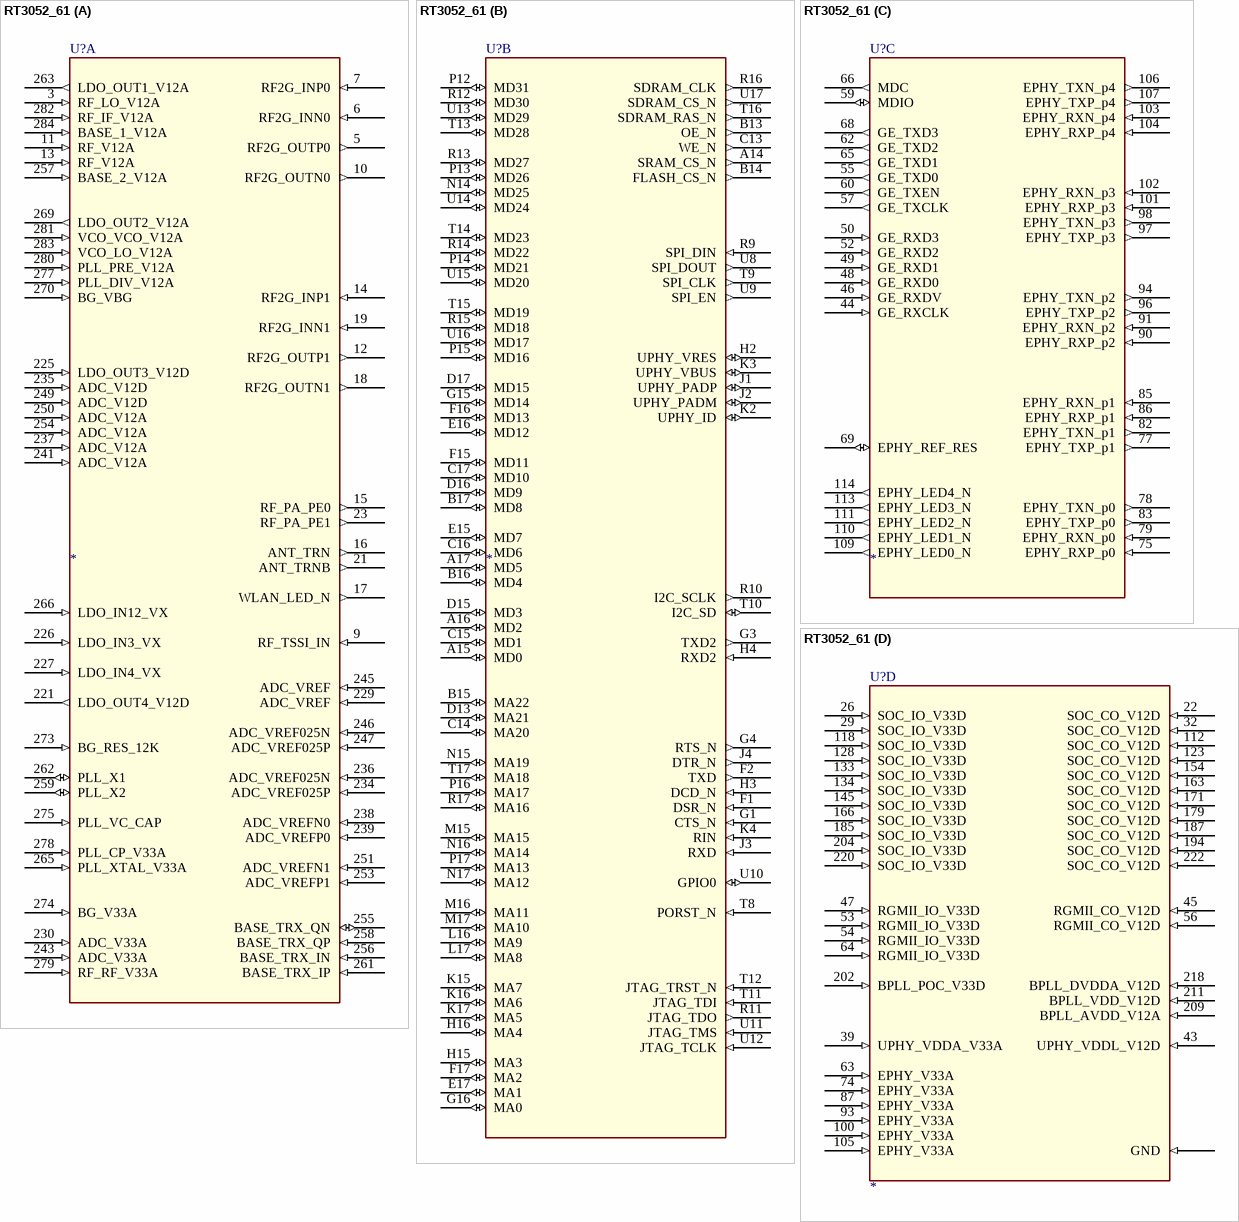
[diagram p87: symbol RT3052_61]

## RT3052_61
designator U?
footprint TFBGA289
part A pins: 3 RF_LO_V12A (in), 5 RF2G_OUTP0 (out), 6 RF2G_INN0 (in), 7 RF2G_INP0 (in), 9 RF_TSSI_IN (in), 10 RF2G_OUTN0 (out), 11 RF_V12A (in), 12 RF2G_OUTP1 (out), 13 RF_V12A (in), 14 RF2G_INP1 (in), 15 RF_PA_PE0 (out), 16 ANT_TRN (out), 17 WLAN_LED_N (out), 18 RF2G_OUTN1 (out), 19 RF2G_INN1 (in), 21 ANT_TRNB (out), 23 RF_PA_PE1 (out), 221 LDO_OUT4_V12D (out), 225 LDO_OUT3_V12D (in), 226 LDO_IN3_VX (in), 227 LDO_IN4_VX (in), 229 ADC_VREF (in), 230 ADC_V33A (in), 234 ADC_VREF025P (in), 235 ADC_V12D (in), 236 ADC_VREF025N (in), 237 ADC_V12A (in), 238 ADC_VREFN0 (in), 239 ADC_VREFP0 (in), 241 ADC_V12A (in), 243 ADC_V33A (in), 245 ADC_VREF (in), 246 ADC_VREF025N (in), 247 ADC_VREF025P (in), 249 ADC_V12D (in), 250 ADC_V12A (in), 251 ADC_VREFN1 (in), 253 ADC_VREFP1 (in), 254 ADC_V12A (in), 255 BASE_TRX_QN (io), 256 BASE_TRX_IN (in), 257 BASE_2_V12A (in), 258 BASE_TRX_QP (in), 259 PLL_X2 (io), 261 BASE_TRX_IP (in), 262 PLL_X1 (io), 263 LDO_OUT1_V12A (out), 265 PLL_XTAL_V33A (in), 266 LDO_IN12_VX (in), 269 LDO_OUT2_V12A (out), 270 BG_VBG (in), 273 BG_RES_12K (in), 274 BG_V33A (in), 275 PLL_VC_CAP (in), 277 PLL_DIV_V12A (in), 278 PLL_CP_V33A (in), 279 RF_RF_V33A (in), 280 PLL_PRE_V12A (in), 281 VCO_VCO_V12A (in), 282 RF_IF_V12A (in), 283 VCO_LO_V12A (in), 284 BASE_1_V12A (in)
part B pins: A14 SRAM_CS_N (out), A15 MD0 (io), A16 MD2 (io), A17 MD5 (io), B13 OE_N (out), B14 FLASH_CS_N (out), B15 MA22 (io), B16 MD4 (io), B17 MD8 (io), C13 WE_N (out), C14 MA20 (io), C15 MD1 (io), C16 MD6 (io), C17 MD10 (io), D13 MA21 (io), D15 MD3 (io), D16 MD9 (io), D17 MD15 (io), E15 MD7 (io), E16 MD12 (io), E17 MA1 (io), F1 DSR_N (in), F2 TXD (out), F15 MD11 (io), F16 MD13 (io), F17 MA2 (io), G1 CTS_N (in), G3 TXD2 (out), G4 RTS_N (out), G15 MD14 (io), G16 MA0 (io), H2 UPHY_VRES (io), H3 DCD_N (in), H4 RXD2 (in), H15 MA3 (io), H16 MA4 (io), J1 UPHY_PADP (io), J2 UPHY_PADM (io), J3 RXD (in), J4 DTR_N (out), K2 UPHY_ID (io), K3 UPHY_VBUS (io), K4 RIN (in), K15 MA7 (io), K16 MA6 (io), K17 MA5 (io), L16 MA9 (io), L17 MA8 (io), M15 MA15 (io), M16 MA11 (io), M17 MA10 (io), N14 MD25 (io), N15 MA19 (io), N16 MA14 (io), N17 MA12 (io), P12 MD31 (io), P13 MD26 (io), P14 MD21 (io), P15 MD16 (io), P16 MA17 (io), P17 MA13 (io), R9 SPI_DIN (in), R10 I2C_SCLK (out), R11 JTAG_TDO (out), R12 MD30 (io), R13 MD27 (io), R14 MD22 (io), R15 MD18 (io), R16 SDRAM_CLK (out), R17 MA16 (io), T8 PORST_N (in), T9 SPI_CLK (out), T10 I2C_SD (io), T11 JTAG_TDI (in), T12 JTAG_TRST_N (in), T13 MD28 (io), T14 MD23 (io), T15 MD19 (io), T16 SDRAM_RAS_N (out), T17 MA18 (io), U8 SPI_DOUT (out), U9 SPI_EN (out), U10 GPIO0 (io), U11 JTAG_TMS (in), U12 JTAG_TCLK (in), U13 MD29 (io), U14 MD24 (io), U15 MD20 (io), U16 MD17 (io), U17 SDRAM_CS_N (out)
part C pins: 44 GE_RXCLK (in), 46 GE_RXDV (in), 48 GE_RXD0 (in), 49 GE_RXD1 (in), 50 GE_RXD3 (in), 52 GE_RXD2 (in), 55 GE_TXD0 (out), 57 GE_TXCLK (out), 59 MDIO (io), 60 GE_TXEN (out), 62 GE_TXD2 (out), 65 GE_TXD1 (out), 66 MDC (out), 68 GE_TXD3 (out), 69 EPHY_REF_RES (io), 75 EPHY_RXP_p0 (in), 77 EPHY_TXP_p1 (out), 78 EPHY_TXN_p0 (out), 79 EPHY_RXN_p0 (in), 82 EPHY_TXN_p1 (out), 83 EPHY_TXP_p0 (out), 85 EPHY_RXN_p1 (in), 86 EPHY_RXP_p1 (in), 90 EPHY_RXP_p2 (in), 91 EPHY_RXN_p2 (in), 94 EPHY_TXN_p2 (out), 96 EPHY_TXP_p2 (out), 97 EPHY_TXP_p3 (out), 98 EPHY_TXN_p3 (out), 101 EPHY_RXP_p3 (in), 102 EPHY_RXN_p3 (in), 103 EPHY_RXN_p4 (in), 104 EPHY_RXP_p4 (in), 106 EPHY_TXN_p4 (out), 107 EPHY_TXP_p4 (out), 109 EPHY_LED0_N (out), 110 EPHY_LED1_N (out), 111 EPHY_LED2_N (out), 113 EPHY_LED3_N (out), 114 EPHY_LED4_N (out)
part D pins: 22 SOC_CO_V12D (in), 26 SOC_IO_V33D (in), 29 SOC_IO_V33D (in), 32 SOC_CO_V12D (in), 39 UPHY_VDDA_V33A (in), 43 UPHY_VDDL_V12D (in), 45 RGMII_CO_V12D (in), 47 RGMII_IO_V33D (in), 53 RGMII_IO_V33D (in), 54 RGMII_IO_V33D (in), 56 RGMII_CO_V12D (in), 63 EPHY_V33A (in), 64 RGMII_IO_V33D (in), 74 EPHY_V33A (in), 87 EPHY_V33A (in), 93 EPHY_V33A (in), 100 EPHY_V33A (in), 105 EPHY_V33A (in), 112 SOC_CO_V12D (in), 118 SOC_IO_V33D (in), 123 SOC_CO_V12D (in), 128 SOC_IO_V33D (in), 133 SOC_IO_V33D (in), 134 SOC_IO_V33D (in), 145 SOC_IO_V33D (in), 154 SOC_CO_V12D (in), 163 SOC_CO_V12D (in), 166 SOC_IO_V33D (in), 171 SOC_CO_V12D (in), 179 SOC_CO_V12D (in), 185 SOC_IO_V33D (in), 187 SOC_CO_V12D (in), 194 SOC_CO_V12D (in), 202 BPLL_POC_V33D (in), 204 SOC_IO_V33D (in), 209 BPLL_AVDD_V12A (in), 211 BPLL_VDD_V12D (in), 218 BPLL_DVDDA_V12D (in), 220 SOC_IO_V33D (in), 222 SOC_CO_V12D (in), GND (in)

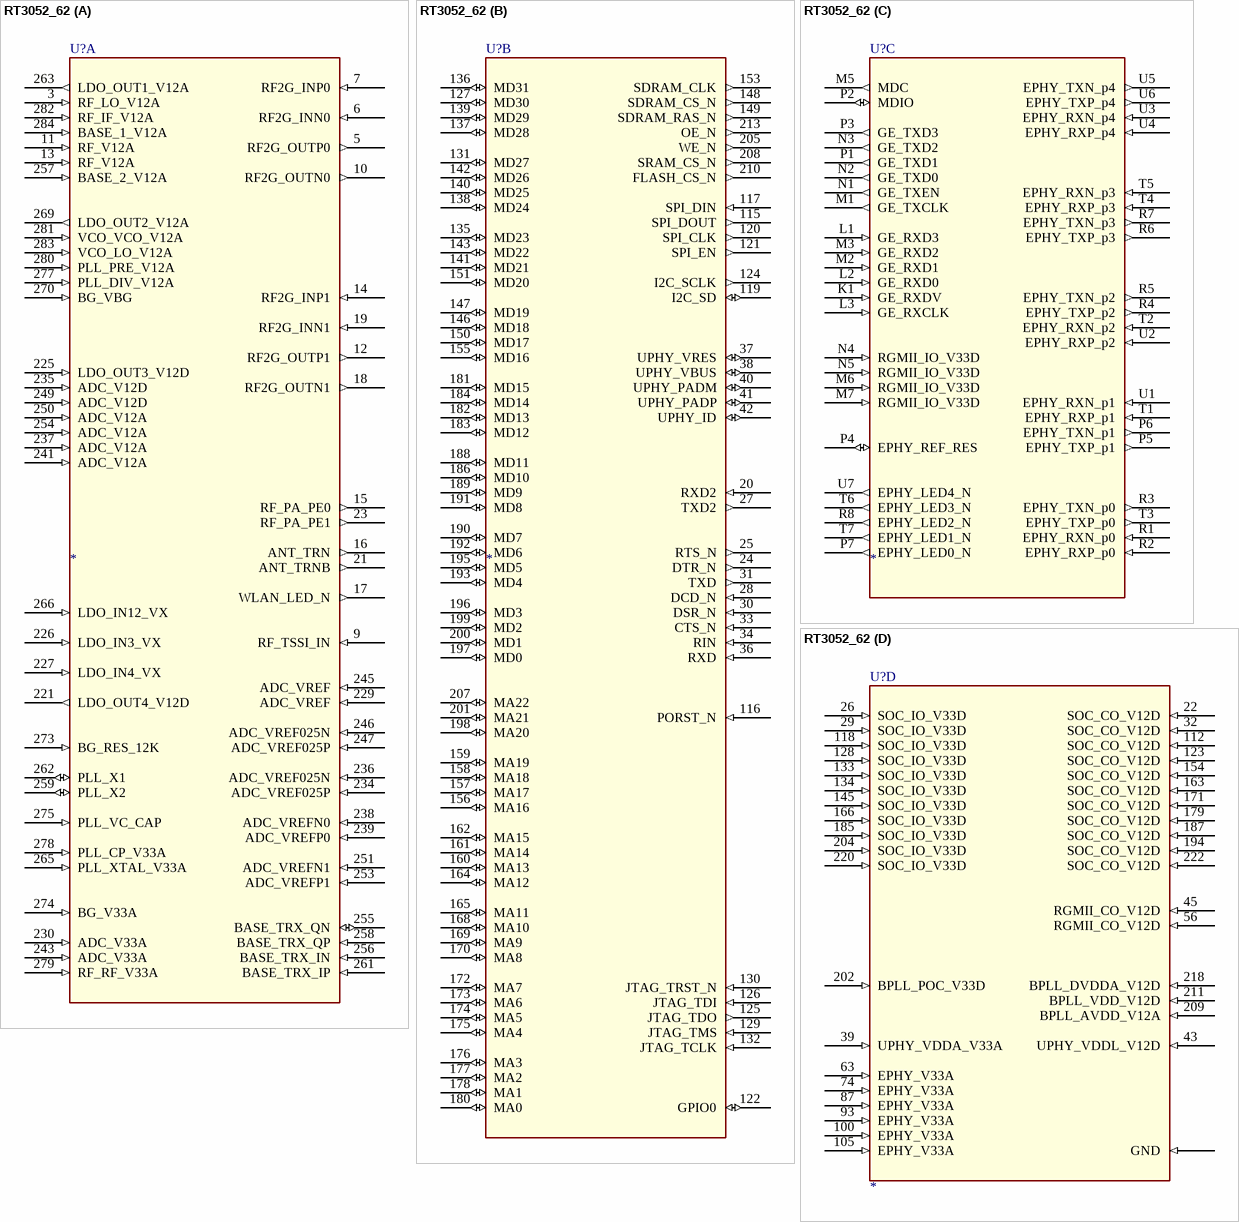
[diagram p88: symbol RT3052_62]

## RT3052_62
designator U?
footprint TFBGA289
part A pins: 3 RF_LO_V12A (in), 5 RF2G_OUTP0 (out), 6 RF2G_INN0 (in), 7 RF2G_INP0 (in), 9 RF_TSSI_IN (in), 10 RF2G_OUTN0 (out), 11 RF_V12A (in), 12 RF2G_OUTP1 (out), 13 RF_V12A (in), 14 RF2G_INP1 (in), 15 RF_PA_PE0 (out), 16 ANT_TRN (out), 17 WLAN_LED_N (out), 18 RF2G_OUTN1 (out), 19 RF2G_INN1 (in), 21 ANT_TRNB (out), 23 RF_PA_PE1 (out), 221 LDO_OUT4_V12D (out), 225 LDO_OUT3_V12D (in), 226 LDO_IN3_VX (in), 227 LDO_IN4_VX (in), 229 ADC_VREF (in), 230 ADC_V33A (in), 234 ADC_VREF025P (in), 235 ADC_V12D (in), 236 ADC_VREF025N (in), 237 ADC_V12A (in), 238 ADC_VREFN0 (in), 239 ADC_VREFP0 (in), 241 ADC_V12A (in), 243 ADC_V33A (in), 245 ADC_VREF (in), 246 ADC_VREF025N (in), 247 ADC_VREF025P (in), 249 ADC_V12D (in), 250 ADC_V12A (in), 251 ADC_VREFN1 (in), 253 ADC_VREFP1 (in), 254 ADC_V12A (in), 255 BASE_TRX_QN (io), 256 BASE_TRX_IN (in), 257 BASE_2_V12A (in), 258 BASE_TRX_QP (in), 259 PLL_X2 (io), 261 BASE_TRX_IP (in), 262 PLL_X1 (io), 263 LDO_OUT1_V12A (out), 265 PLL_XTAL_V33A (in), 266 LDO_IN12_VX (in), 269 LDO_OUT2_V12A (out), 270 BG_VBG (in), 273 BG_RES_12K (in), 274 BG_V33A (in), 275 PLL_VC_CAP (in), 277 PLL_DIV_V12A (in), 278 PLL_CP_V33A (in), 279 RF_RF_V33A (in), 280 PLL_PRE_V12A (in), 281 VCO_VCO_V12A (in), 282 RF_IF_V12A (in), 283 VCO_LO_V12A (in), 284 BASE_1_V12A (in)
part B pins: 20 RXD2 (in), 24 DTR_N (out), 25 RTS_N (out), 27 TXD2 (out), 28 DCD_N (in), 30 DSR_N (in), 31 TXD (out), 33 CTS_N (in), 34 RIN (in), 36 RXD (in), 37 UPHY_VRES (io), 38 UPHY_VBUS (io), 40 UPHY_PADM (io), 41 UPHY_PADP (io), 42 UPHY_ID (io), 115 SPI_DOUT (out), 116 PORST_N (in), 117 SPI_DIN (in), 119 I2C_SD (io), 120 SPI_CLK (out), 121 SPI_EN (out), 122 GPIO0 (io), 124 I2C_SCLK (out), 125 JTAG_TDO (out), 126 JTAG_TDI (in), 127 MD30 (io), 129 JTAG_TMS (in), 130 JTAG_TRST_N (in), 131 MD27 (io), 132 JTAG_TCLK (in), 135 MD23 (io), 136 MD31 (io), 137 MD28 (io), 138 MD24 (io), 139 MD29 (io), 140 MD25 (io), 141 MD21 (io), 142 MD26 (io), 143 MD22 (io), 146 MD18 (io), 147 MD19 (io), 148 SDRAM_CS_N (out), 149 SDRAM_RAS_N (out), 150 MD17 (io), 151 MD20 (io), 153 SDRAM_CLK (out), 155 MD16 (io), 156 MA16 (io), 157 MA17 (io), 158 MA18 (io), 159 MA19 (io), 160 MA13 (io), 161 MA14 (io), 162 MA15 (io), 164 MA12 (io), 165 MA11 (io), 168 MA10 (io), 169 MA9 (io), 170 MA8 (io), 172 MA7 (io), 173 MA6 (io), 174 MA5 (io), 175 MA4 (io), 176 MA3 (io), 177 MA2 (io), 178 MA1 (io), 180 MA0 (io), 181 MD15 (io), 182 MD13 (io), 183 MD12 (io), 184 MD14 (io), 186 MD10 (io), 188 MD11 (io), 189 MD9 (io), 190 MD7 (io), 191 MD8 (io), 192 MD6 (io), 193 MD4 (io), 195 MD5 (io), 196 MD3 (io), 197 MD0 (io), 198 MA20 (io), 199 MD2 (io), 200 MD1 (io), 201 MA21 (io), 205 WE_N (out), 207 MA22 (io), 208 SRAM_CS_N (out), 210 FLASH_CS_N (out), 213 OE_N (out)
part C pins: K1 GE_RXDV (in), L1 GE_RXD3 (in), L2 GE_RXD0 (in), L3 GE_RXCLK (in), M1 GE_TXCLK (out), M2 GE_RXD1 (in), M3 GE_RXD2 (in), M5 MDC (out), M6 RGMII_IO_V33D (in), M7 RGMII_IO_V33D (in), N1 GE_TXEN (out), N2 GE_TXD0 (out), N3 GE_TXD2 (out), N4 RGMII_IO_V33D (in), N5 RGMII_IO_V33D (in), P1 GE_TXD1 (out), P2 MDIO (io), P3 GE_TXD3 (out), P4 EPHY_REF_RES (io), P5 EPHY_TXP_p1 (out), P6 EPHY_TXN_p1 (out), P7 EPHY_LED0_N (out), R1 EPHY_RXN_p0 (in), R2 EPHY_RXP_p0 (in), R3 EPHY_TXN_p0 (out), R4 EPHY_TXP_p2 (out), R5 EPHY_TXN_p2 (out), R6 EPHY_TXP_p3 (out), R7 EPHY_TXN_p3 (out), R8 EPHY_LED2_N (out), T1 EPHY_RXP_p1 (in), T2 EPHY_RXN_p2 (in), T3 EPHY_TXP_p0 (out), T4 EPHY_RXP_p3 (in), T5 EPHY_RXN_p3 (in), T6 EPHY_LED3_N (out), T7 EPHY_LED1_N (out), U1 EPHY_RXN_p1 (in), U2 EPHY_RXP_p2 (in), U3 EPHY_RXN_p4 (in), U4 EPHY_RXP_p4 (in), U5 EPHY_TXN_p4 (out), U6 EPHY_TXP_p4 (out), U7 EPHY_LED4_N (out)
part D pins: 22 SOC_CO_V12D (in), 26 SOC_IO_V33D (in), 29 SOC_IO_V33D (in), 32 SOC_CO_V12D (in), 39 UPHY_VDDA_V33A (in), 43 UPHY_VDDL_V12D (in), 45 RGMII_CO_V12D (in), 56 RGMII_CO_V12D (in), 63 EPHY_V33A (in), 74 EPHY_V33A (in), 87 EPHY_V33A (in), 93 EPHY_V33A (in), 100 EPHY_V33A (in), 105 EPHY_V33A (in), 112 SOC_CO_V12D (in), 118 SOC_IO_V33D (in), 123 SOC_CO_V12D (in), 128 SOC_IO_V33D (in), 133 SOC_IO_V33D (in), 134 SOC_IO_V33D (in), 145 SOC_IO_V33D (in), 154 SOC_CO_V12D (in), 163 SOC_CO_V12D (in), 166 SOC_IO_V33D (in), 171 SOC_CO_V12D (in), 179 SOC_CO_V12D (in), 185 SOC_IO_V33D (in), 187 SOC_CO_V12D (in), 194 SOC_CO_V12D (in), 202 BPLL_POC_V33D (in), 204 SOC_IO_V33D (in), 209 BPLL_AVDD_V12A (in), 211 BPLL_VDD_V12D (in), 218 BPLL_DVDDA_V12D (in), 220 SOC_IO_V33D (in), 222 SOC_CO_V12D (in), GND (in)

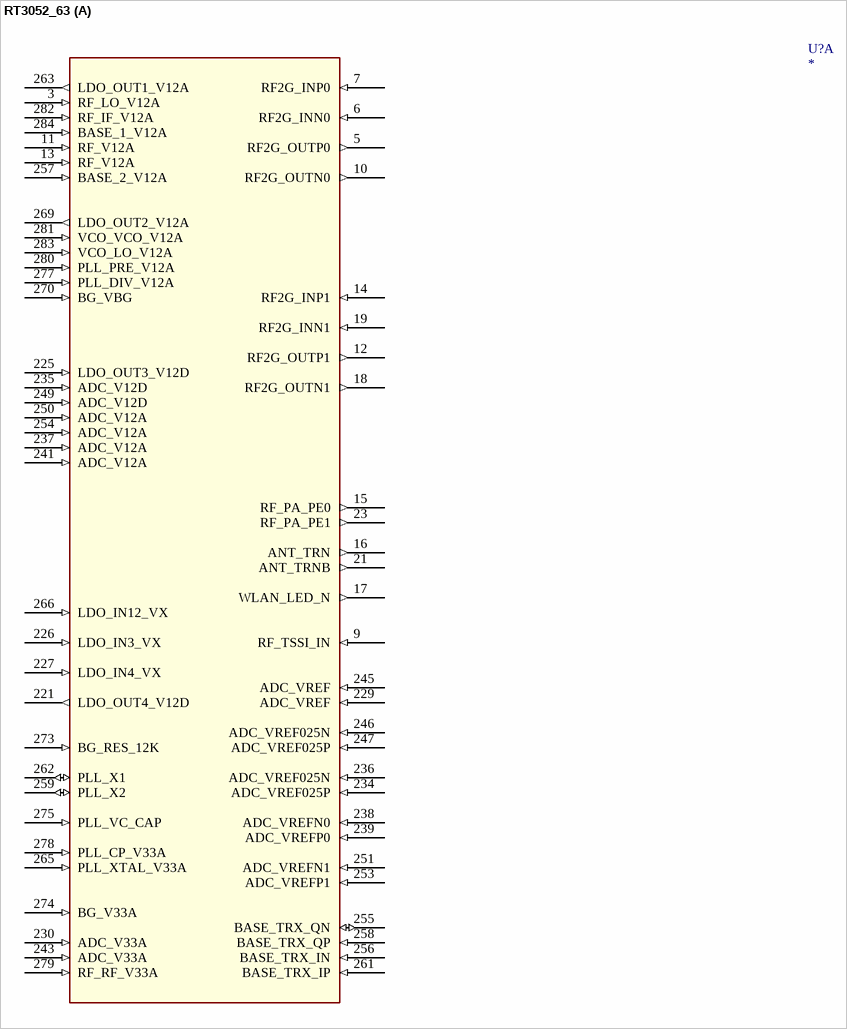
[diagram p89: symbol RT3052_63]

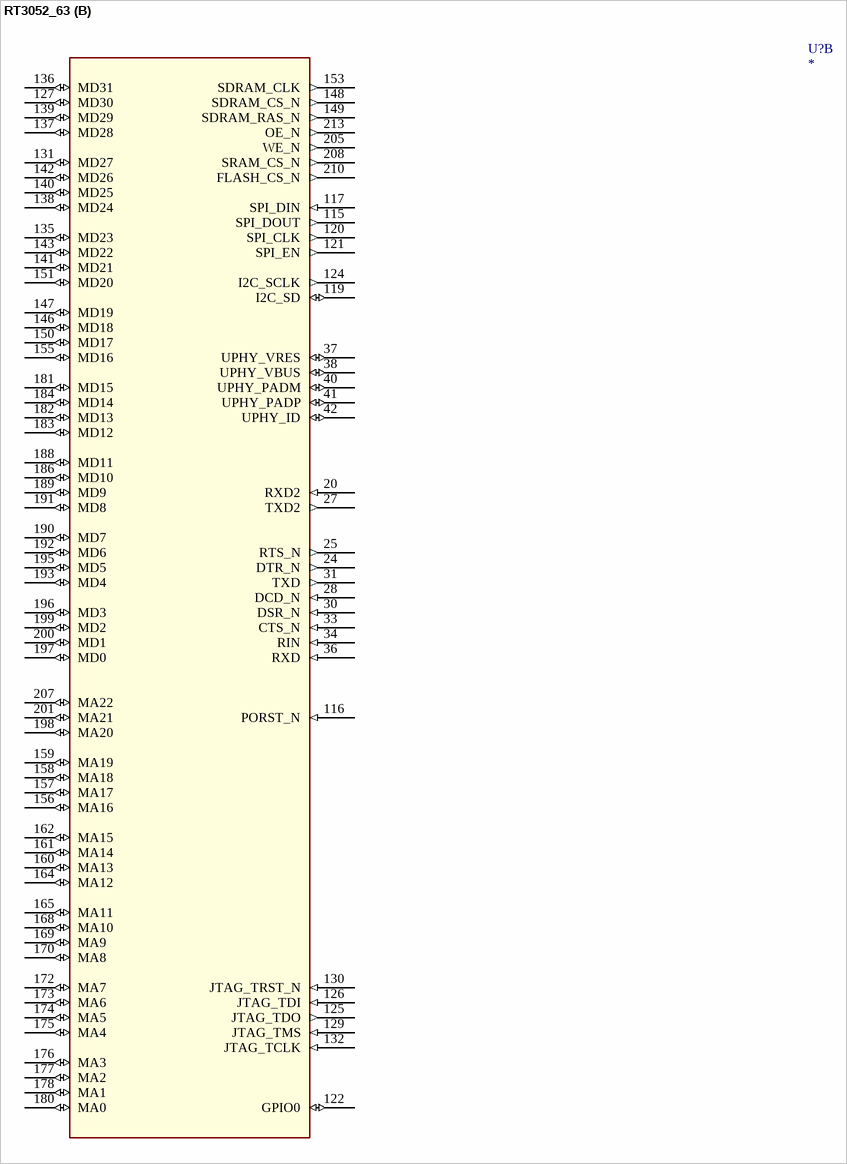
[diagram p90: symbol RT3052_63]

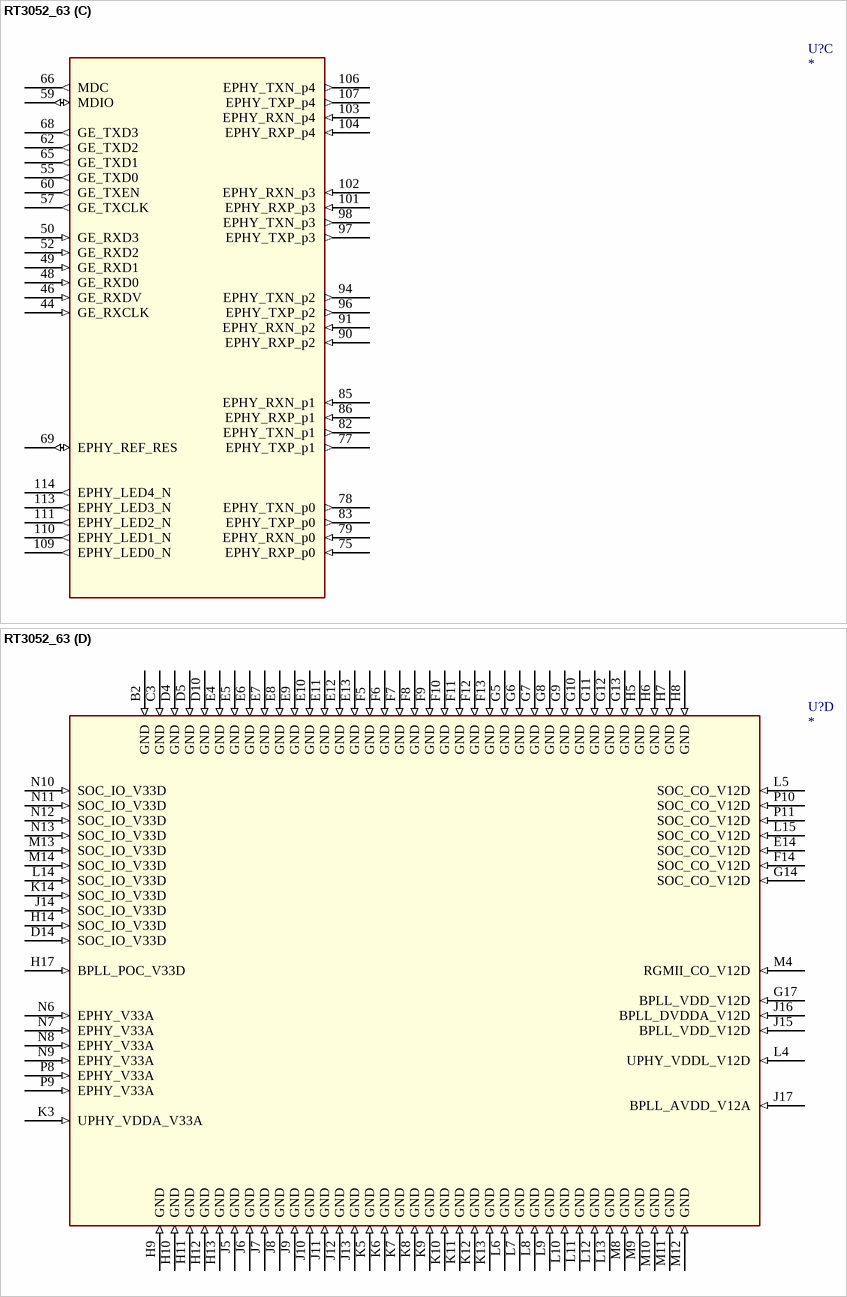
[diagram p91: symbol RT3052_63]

## RT3052_63
designator U?
footprint TFBGA289
part A pins: 3 RF_LO_V12A (in), 5 RF2G_OUTP0 (out), 6 RF2G_INN0 (in), 7 RF2G_INP0 (in), 9 RF_TSSI_IN (in), 10 RF2G_OUTN0 (out), 11 RF_V12A (in), 12 RF2G_OUTP1 (out), 13 RF_V12A (in), 14 RF2G_INP1 (in), 15 RF_PA_PE0 (out), 16 ANT_TRN (out), 17 WLAN_LED_N (out), 18 RF2G_OUTN1 (out), 19 RF2G_INN1 (in), 21 ANT_TRNB (out), 23 RF_PA_PE1 (out), 221 LDO_OUT4_V12D (out), 225 LDO_OUT3_V12D (in), 226 LDO_IN3_VX (in), 227 LDO_IN4_VX (in), 229 ADC_VREF (in), 230 ADC_V33A (in), 234 ADC_VREF025P (in), 235 ADC_V12D (in), 236 ADC_VREF025N (in), 237 ADC_V12A (in), 238 ADC_VREFN0 (in), 239 ADC_VREFP0 (in), 241 ADC_V12A (in), 243 ADC_V33A (in), 245 ADC_VREF (in), 246 ADC_VREF025N (in), 247 ADC_VREF025P (in), 249 ADC_V12D (in), 250 ADC_V12A (in), 251 ADC_VREFN1 (in), 253 ADC_VREFP1 (in), 254 ADC_V12A (in), 255 BASE_TRX_QN (io), 256 BASE_TRX_IN (in), 257 BASE_2_V12A (in), 258 BASE_TRX_QP (in), 259 PLL_X2 (io), 261 BASE_TRX_IP (in), 262 PLL_X1 (io), 263 LDO_OUT1_V12A (out), 265 PLL_XTAL_V33A (in), 266 LDO_IN12_VX (in), 269 LDO_OUT2_V12A (out), 270 BG_VBG (in), 273 BG_RES_12K (in), 274 BG_V33A (in), 275 PLL_VC_CAP (in), 277 PLL_DIV_V12A (in), 278 PLL_CP_V33A (in), 279 RF_RF_V33A (in), 280 PLL_PRE_V12A (in), 281 VCO_VCO_V12A (in), 282 RF_IF_V12A (in), 283 VCO_LO_V12A (in), 284 BASE_1_V12A (in)
part B pins: 20 RXD2 (in), 24 DTR_N (out), 25 RTS_N (out), 27 TXD2 (out), 28 DCD_N (in), 30 DSR_N (in), 31 TXD (out), 33 CTS_N (in), 34 RIN (in), 36 RXD (in), 37 UPHY_VRES (io), 38 UPHY_VBUS (io), 40 UPHY_PADM (io), 41 UPHY_PADP (io), 42 UPHY_ID (io), 115 SPI_DOUT (out), 116 PORST_N (in), 117 SPI_DIN (in), 119 I2C_SD (io), 120 SPI_CLK (out), 121 SPI_EN (out), 122 GPIO0 (io), 124 I2C_SCLK (out), 125 JTAG_TDO (out), 126 JTAG_TDI (in), 127 MD30 (io), 129 JTAG_TMS (in), 130 JTAG_TRST_N (in), 131 MD27 (io), 132 JTAG_TCLK (in), 135 MD23 (io), 136 MD31 (io), 137 MD28 (io), 138 MD24 (io), 139 MD29 (io), 140 MD25 (io), 141 MD21 (io), 142 MD26 (io), 143 MD22 (io), 146 MD18 (io), 147 MD19 (io), 148 SDRAM_CS_N (out), 149 SDRAM_RAS_N (out), 150 MD17 (io), 151 MD20 (io), 153 SDRAM_CLK (out), 155 MD16 (io), 156 MA16 (io), 157 MA17 (io), 158 MA18 (io), 159 MA19 (io), 160 MA13 (io), 161 MA14 (io), 162 MA15 (io), 164 MA12 (io), 165 MA11 (io), 168 MA10 (io), 169 MA9 (io), 170 MA8 (io), 172 MA7 (io), 173 MA6 (io), 174 MA5 (io), 175 MA4 (io), 176 MA3 (io), 177 MA2 (io), 178 MA1 (io), 180 MA0 (io), 181 MD15 (io), 182 MD13 (io), 183 MD12 (io), 184 MD14 (io), 186 MD10 (io), 188 MD11 (io), 189 MD9 (io), 190 MD7 (io), 191 MD8 (io), 192 MD6 (io), 193 MD4 (io), 195 MD5 (io), 196 MD3 (io), 197 MD0 (io), 198 MA20 (io), 199 MD2 (io), 200 MD1 (io), 201 MA21 (io), 205 WE_N (out), 207 MA22 (io), 208 SRAM_CS_N (out), 210 FLASH_CS_N (out), 213 OE_N (out)
part C pins: 44 GE_RXCLK (in), 46 GE_RXDV (in), 48 GE_RXD0 (in), 49 GE_RXD1 (in), 50 GE_RXD3 (in), 52 GE_RXD2 (in), 55 GE_TXD0 (out), 57 GE_TXCLK (out), 59 MDIO (io), 60 GE_TXEN (out), 62 GE_TXD2 (out), 65 GE_TXD1 (out), 66 MDC (out), 68 GE_TXD3 (out), 69 EPHY_REF_RES (io), 75 EPHY_RXP_p0 (in), 77 EPHY_TXP_p1 (out), 78 EPHY_TXN_p0 (out), 79 EPHY_RXN_p0 (in), 82 EPHY_TXN_p1 (out), 83 EPHY_TXP_p0 (out), 85 EPHY_RXN_p1 (in), 86 EPHY_RXP_p1 (in), 90 EPHY_RXP_p2 (in), 91 EPHY_RXN_p2 (in), 94 EPHY_TXN_p2 (out), 96 EPHY_TXP_p2 (out), 97 EPHY_TXP_p3 (out), 98 EPHY_TXN_p3 (out), 101 EPHY_RXP_p3 (in), 102 EPHY_RXN_p3 (in), 103 EPHY_RXN_p4 (in), 104 EPHY_RXP_p4 (in), 106 EPHY_TXN_p4 (out), 107 EPHY_TXP_p4 (out), 109 EPHY_LED0_N (out), 110 EPHY_LED1_N (out), 111 EPHY_LED2_N (out), 113 EPHY_LED3_N (out), 114 EPHY_LED4_N (out)
part D pins: B2 GND (in), C3 GND (in), D4 GND (in), D5 GND (in), D10 GND (in), D14 SOC_IO_V33D (in), E4 GND (in), E5 GND (in), E6 GND (in), E7 GND (in), E8 GND (in), E9 GND (in), E10 GND (in), E11 GND (in), E12 GND (in), E13 GND (in), E14 SOC_CO_V12D (in), F5 GND (in), F6 GND (in), F7 GND (in), F8 GND (in), F9 GND (in), F10 GND (in), F11 GND (in), F12 GND (in), F13 GND (in), F14 SOC_CO_V12D (in), G5 GND (in), G6 GND (in), G7 GND (in), G8 GND (in), G9 GND (in), G10 GND (in), G11 GND (in), G12 GND (in), G13 GND (in), G14 SOC_CO_V12D (in), G17 BPLL_VDD_V12D (in), H5 GND (in), H6 GND (in), H7 GND (in), H8 GND (in), H9 GND (in), H10 GND (in), H11 GND (in), H12 GND (in), H13 GND (in), H14 SOC_IO_V33D (in), H17 BPLL_POC_V33D (in), J5 GND (in), J6 GND (in), J7 GND (in), J8 GND (in), J9 GND (in), J10 GND (in), J11 GND (in), J12 GND (in), J13 GND (in), J14 SOC_IO_V33D (in), J15 BPLL_VDD_V12D (in), J16 BPLL_DVDDA_V12D (in), J17 BPLL_AVDD_V12A (in), K3 UPHY_VDDA_V33A (in), K5 GND (in), K6 GND (in), K7 GND (in), K8 GND (in), K9 GND (in), K10 GND (in), K11 GND (in), K12 GND (in), K13 GND (in), K14 SOC_IO_V33D (in), L4 UPHY_VDDL_V12D (in), L5 SOC_CO_V12D (in), L6 GND (in), L7 GND (in), L8 GND (in), L9 GND (in), L10 GND (in), L11 GND (in), L12 GND (in), L13 GND (in), L14 SOC_IO_V33D (in), L15 SOC_CO_V12D (in), M4 RGMII_CO_V12D (in), M8 GND (in), M9 GND (in), M10 GND (in), M11 GND (in), M12 GND (in), M13 SOC_IO_V33D (in), M14 SOC_IO_V33D (in), N6 EPHY_V33A (in), N7 EPHY_V33A (in), N8 EPHY_V33A (in), N9 EPHY_V33A (in), N10 SOC_IO_V33D (in), N11 SOC_IO_V33D (in), N12 SOC_IO_V33D (in), N13 SOC_IO_V33D (in), P8 EPHY_V33A (in), P9 EPHY_V33A (in), P10 SOC_CO_V12D (in), P11 SOC_CO_V12D (in)

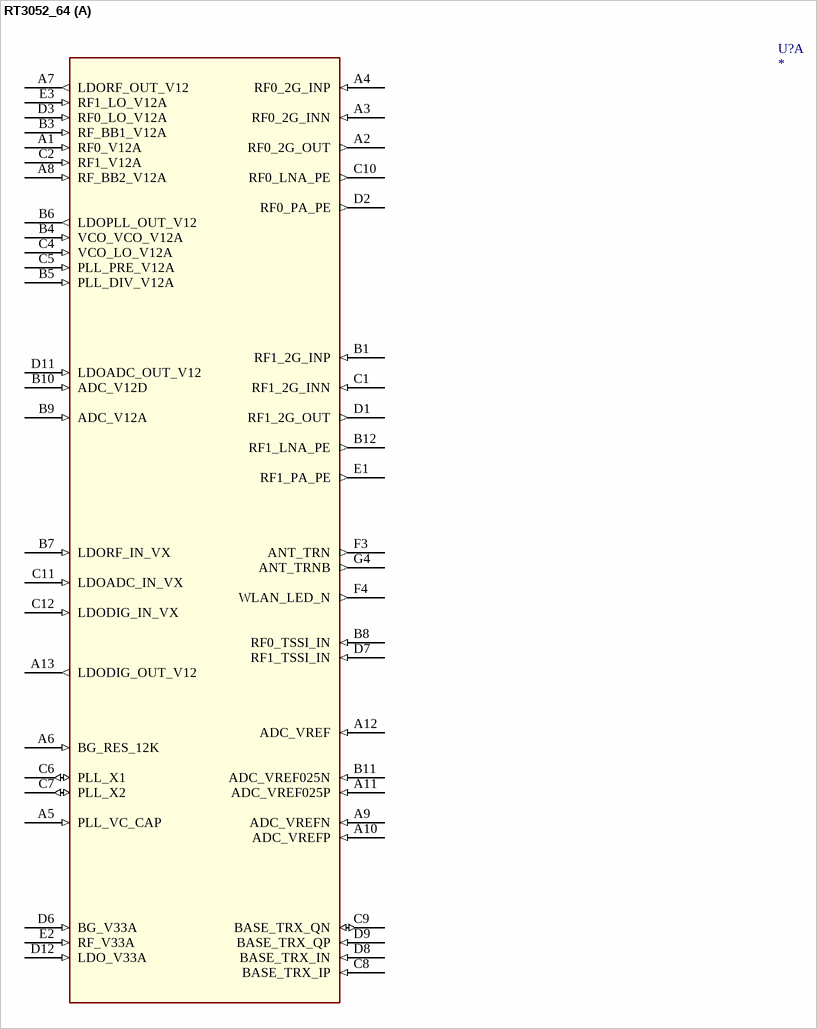
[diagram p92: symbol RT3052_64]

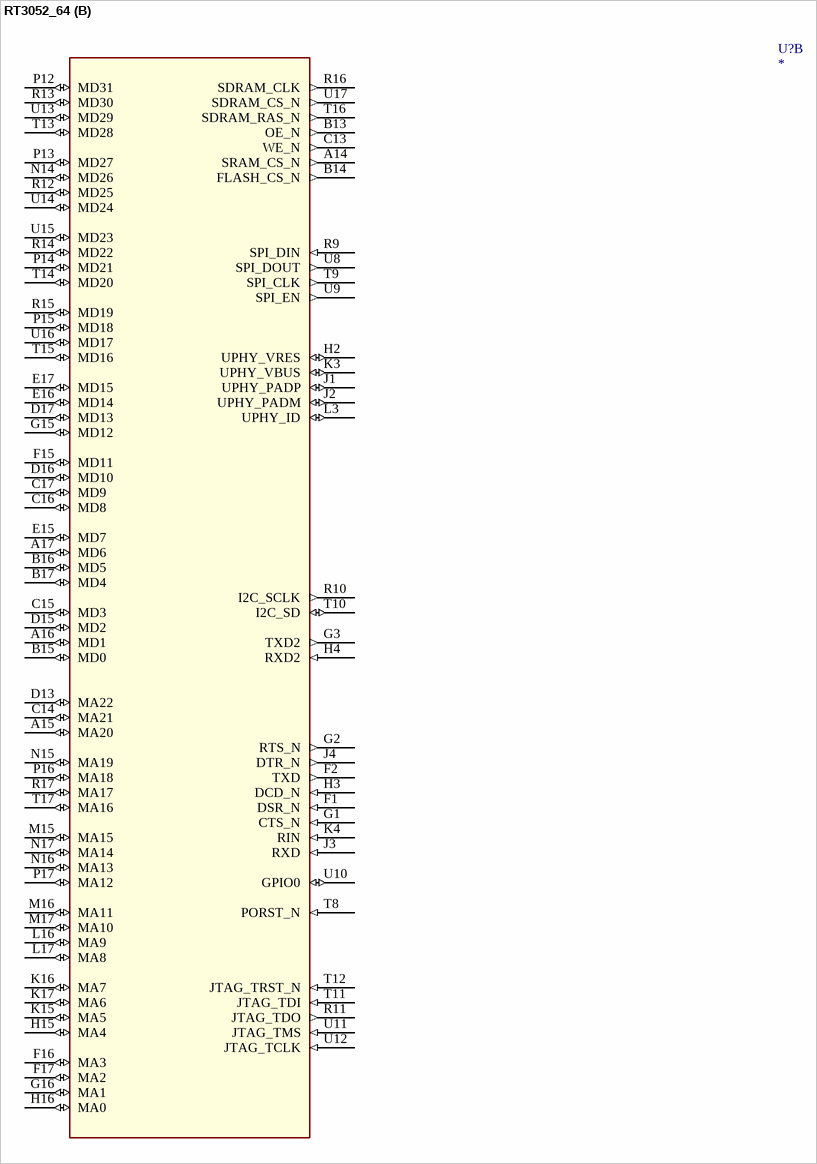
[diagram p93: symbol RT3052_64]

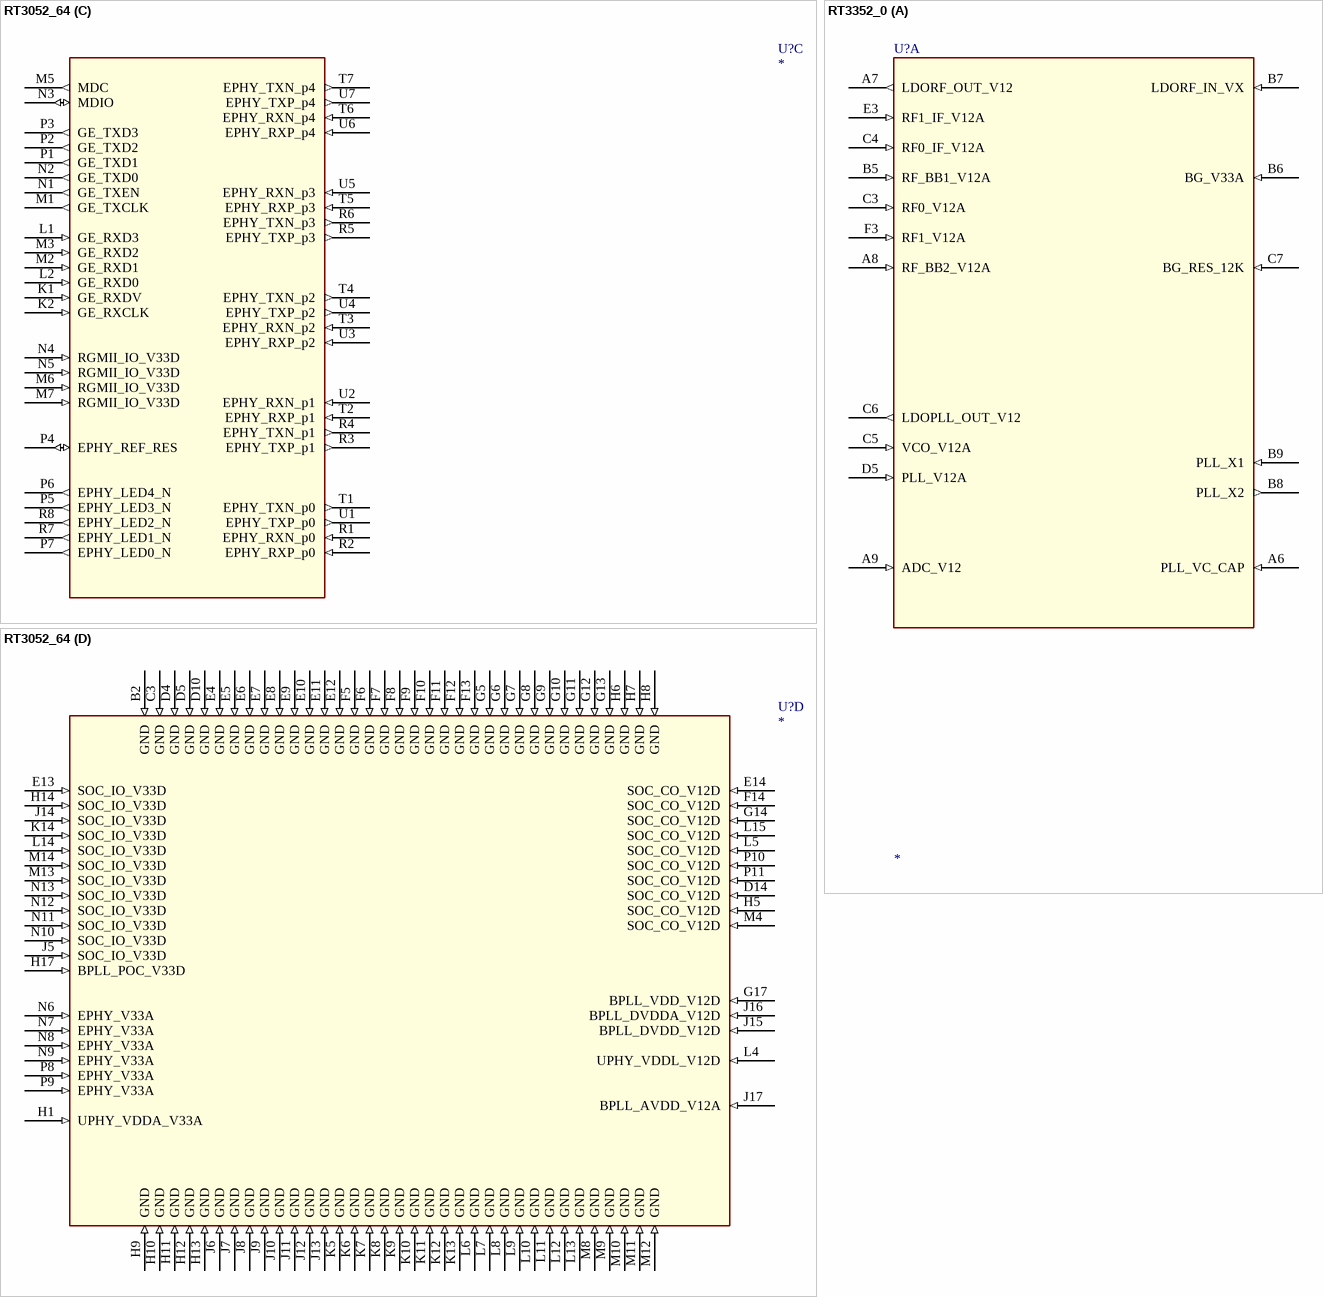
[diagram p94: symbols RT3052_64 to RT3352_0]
